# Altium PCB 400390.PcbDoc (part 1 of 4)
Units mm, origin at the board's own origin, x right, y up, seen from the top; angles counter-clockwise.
Board outline 50.8 x 50.4 mm, 4 copper layers (Top Layer, Mid Layer 1, Mid Layer 2, Bottom Layer), stack 1.507 mm thick; 236 components, 197 nets, 1131 pads, 994 vias.
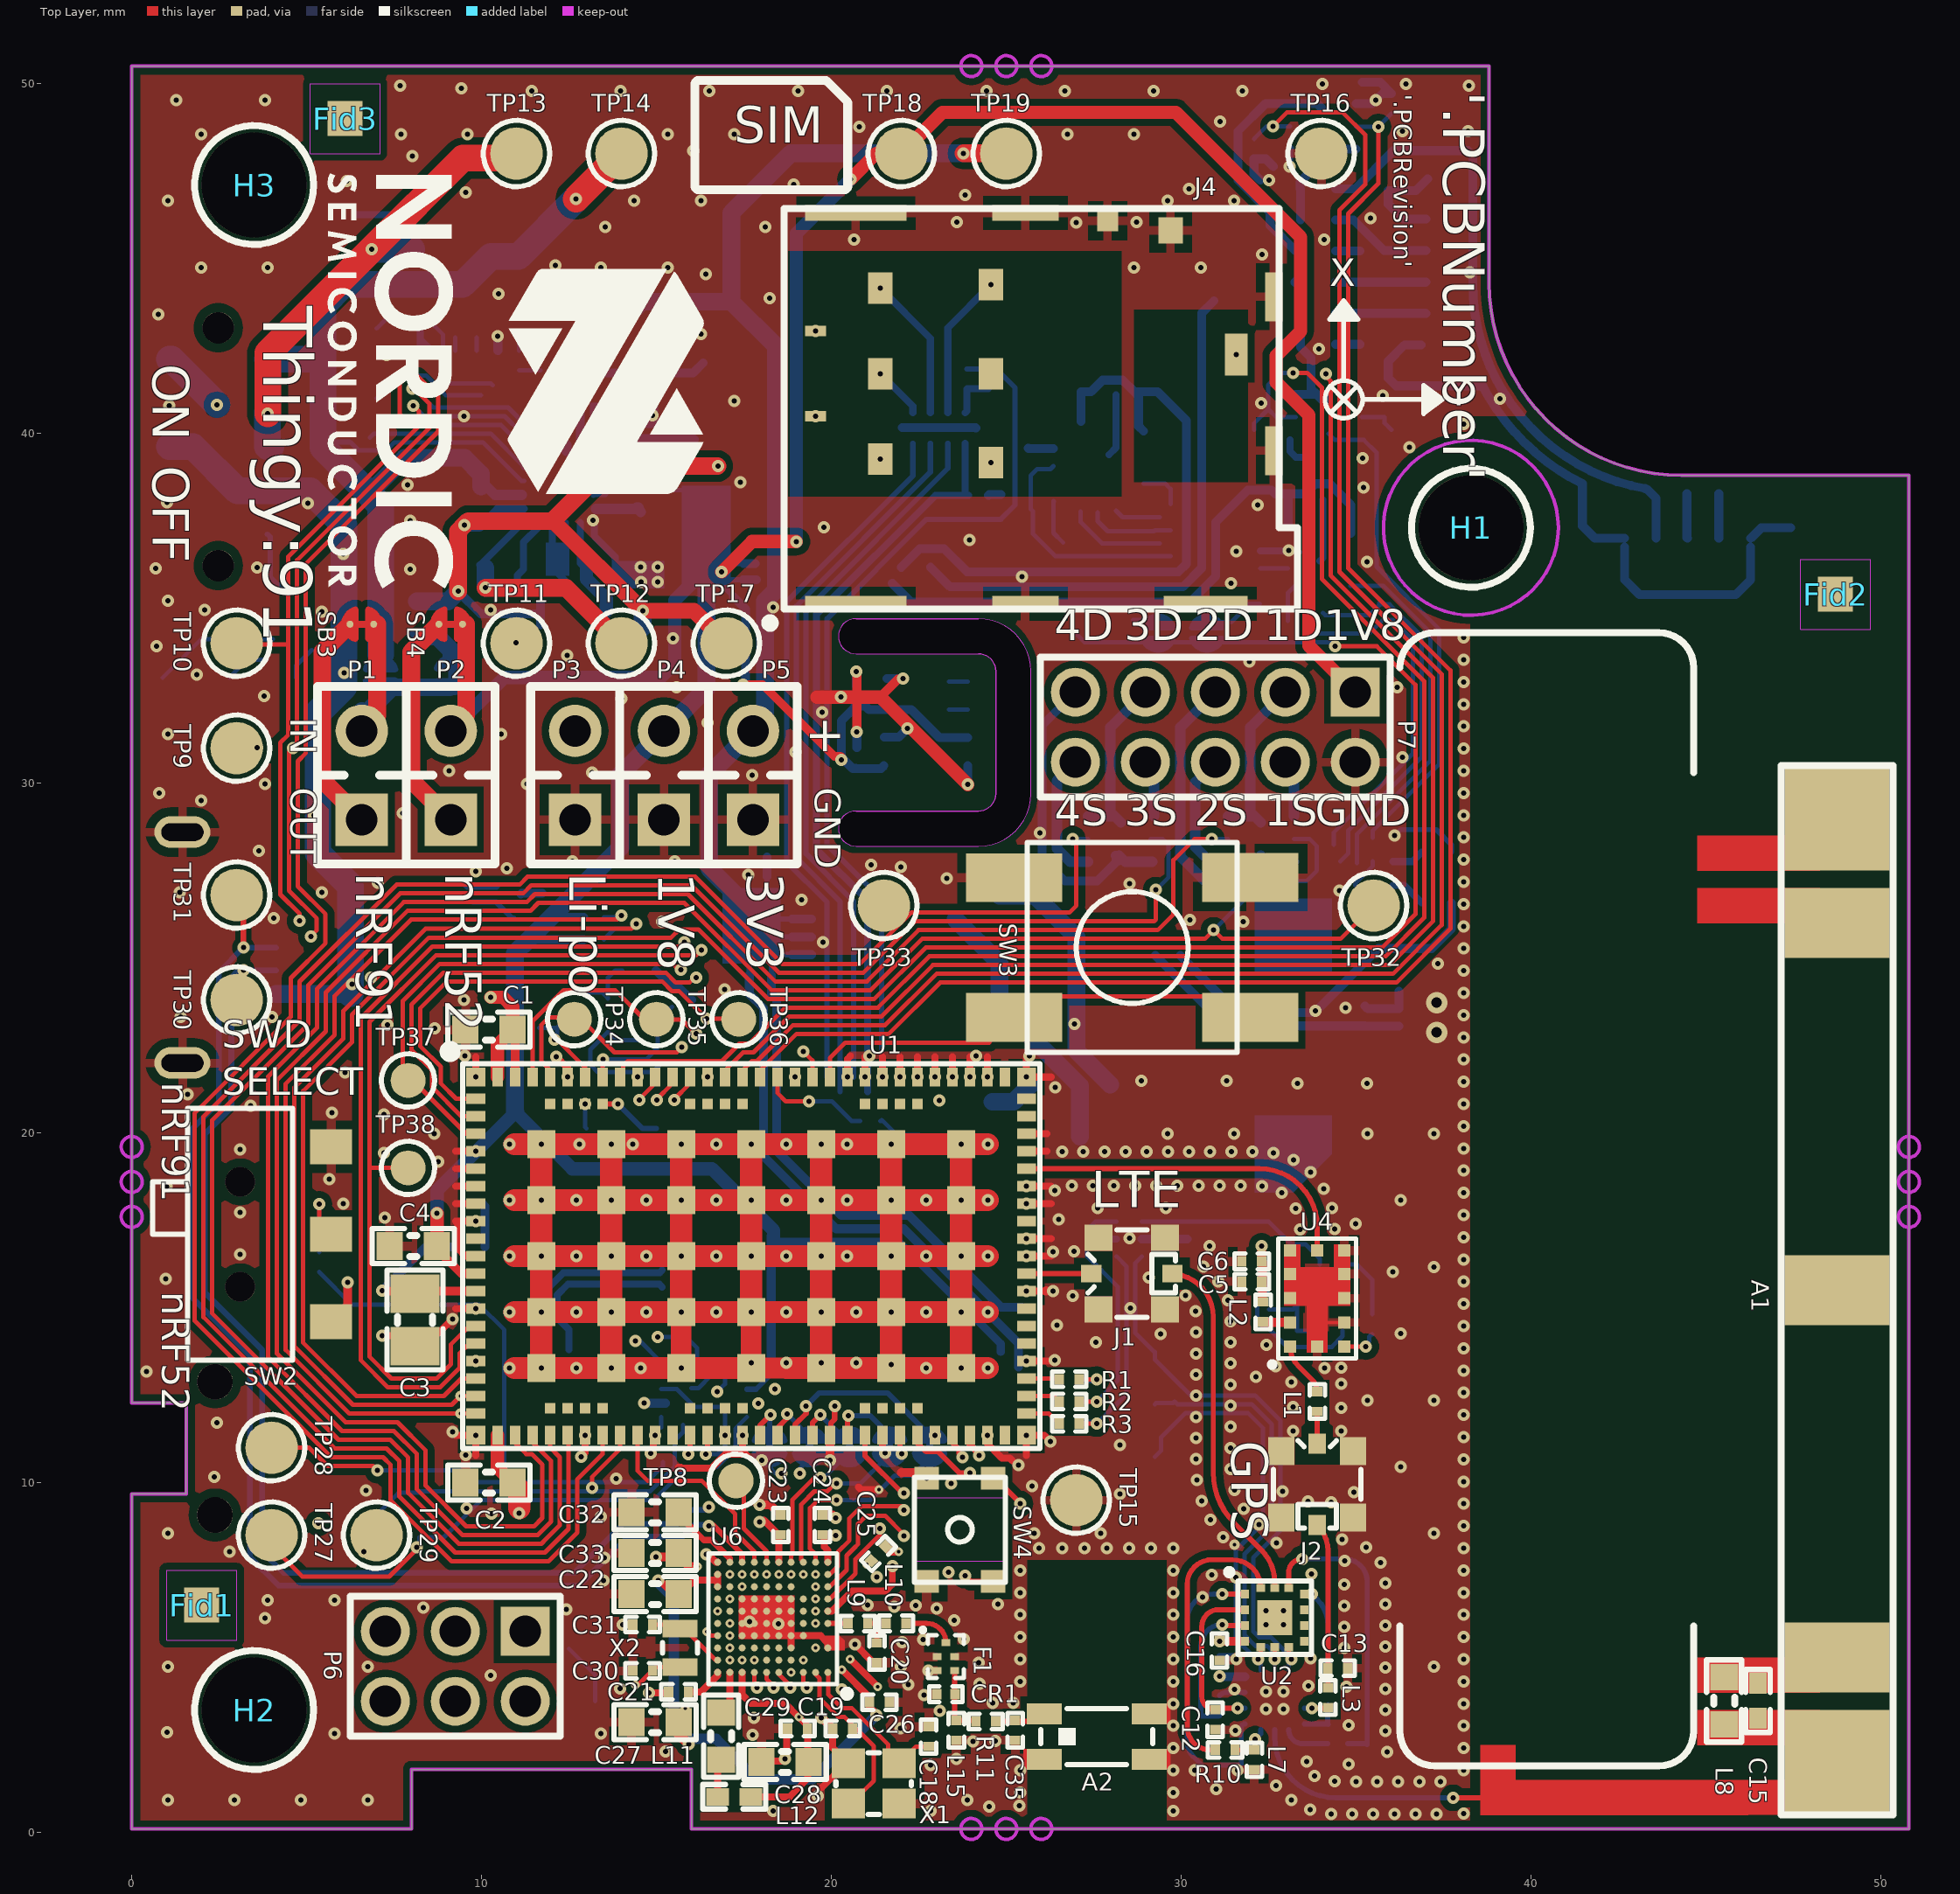
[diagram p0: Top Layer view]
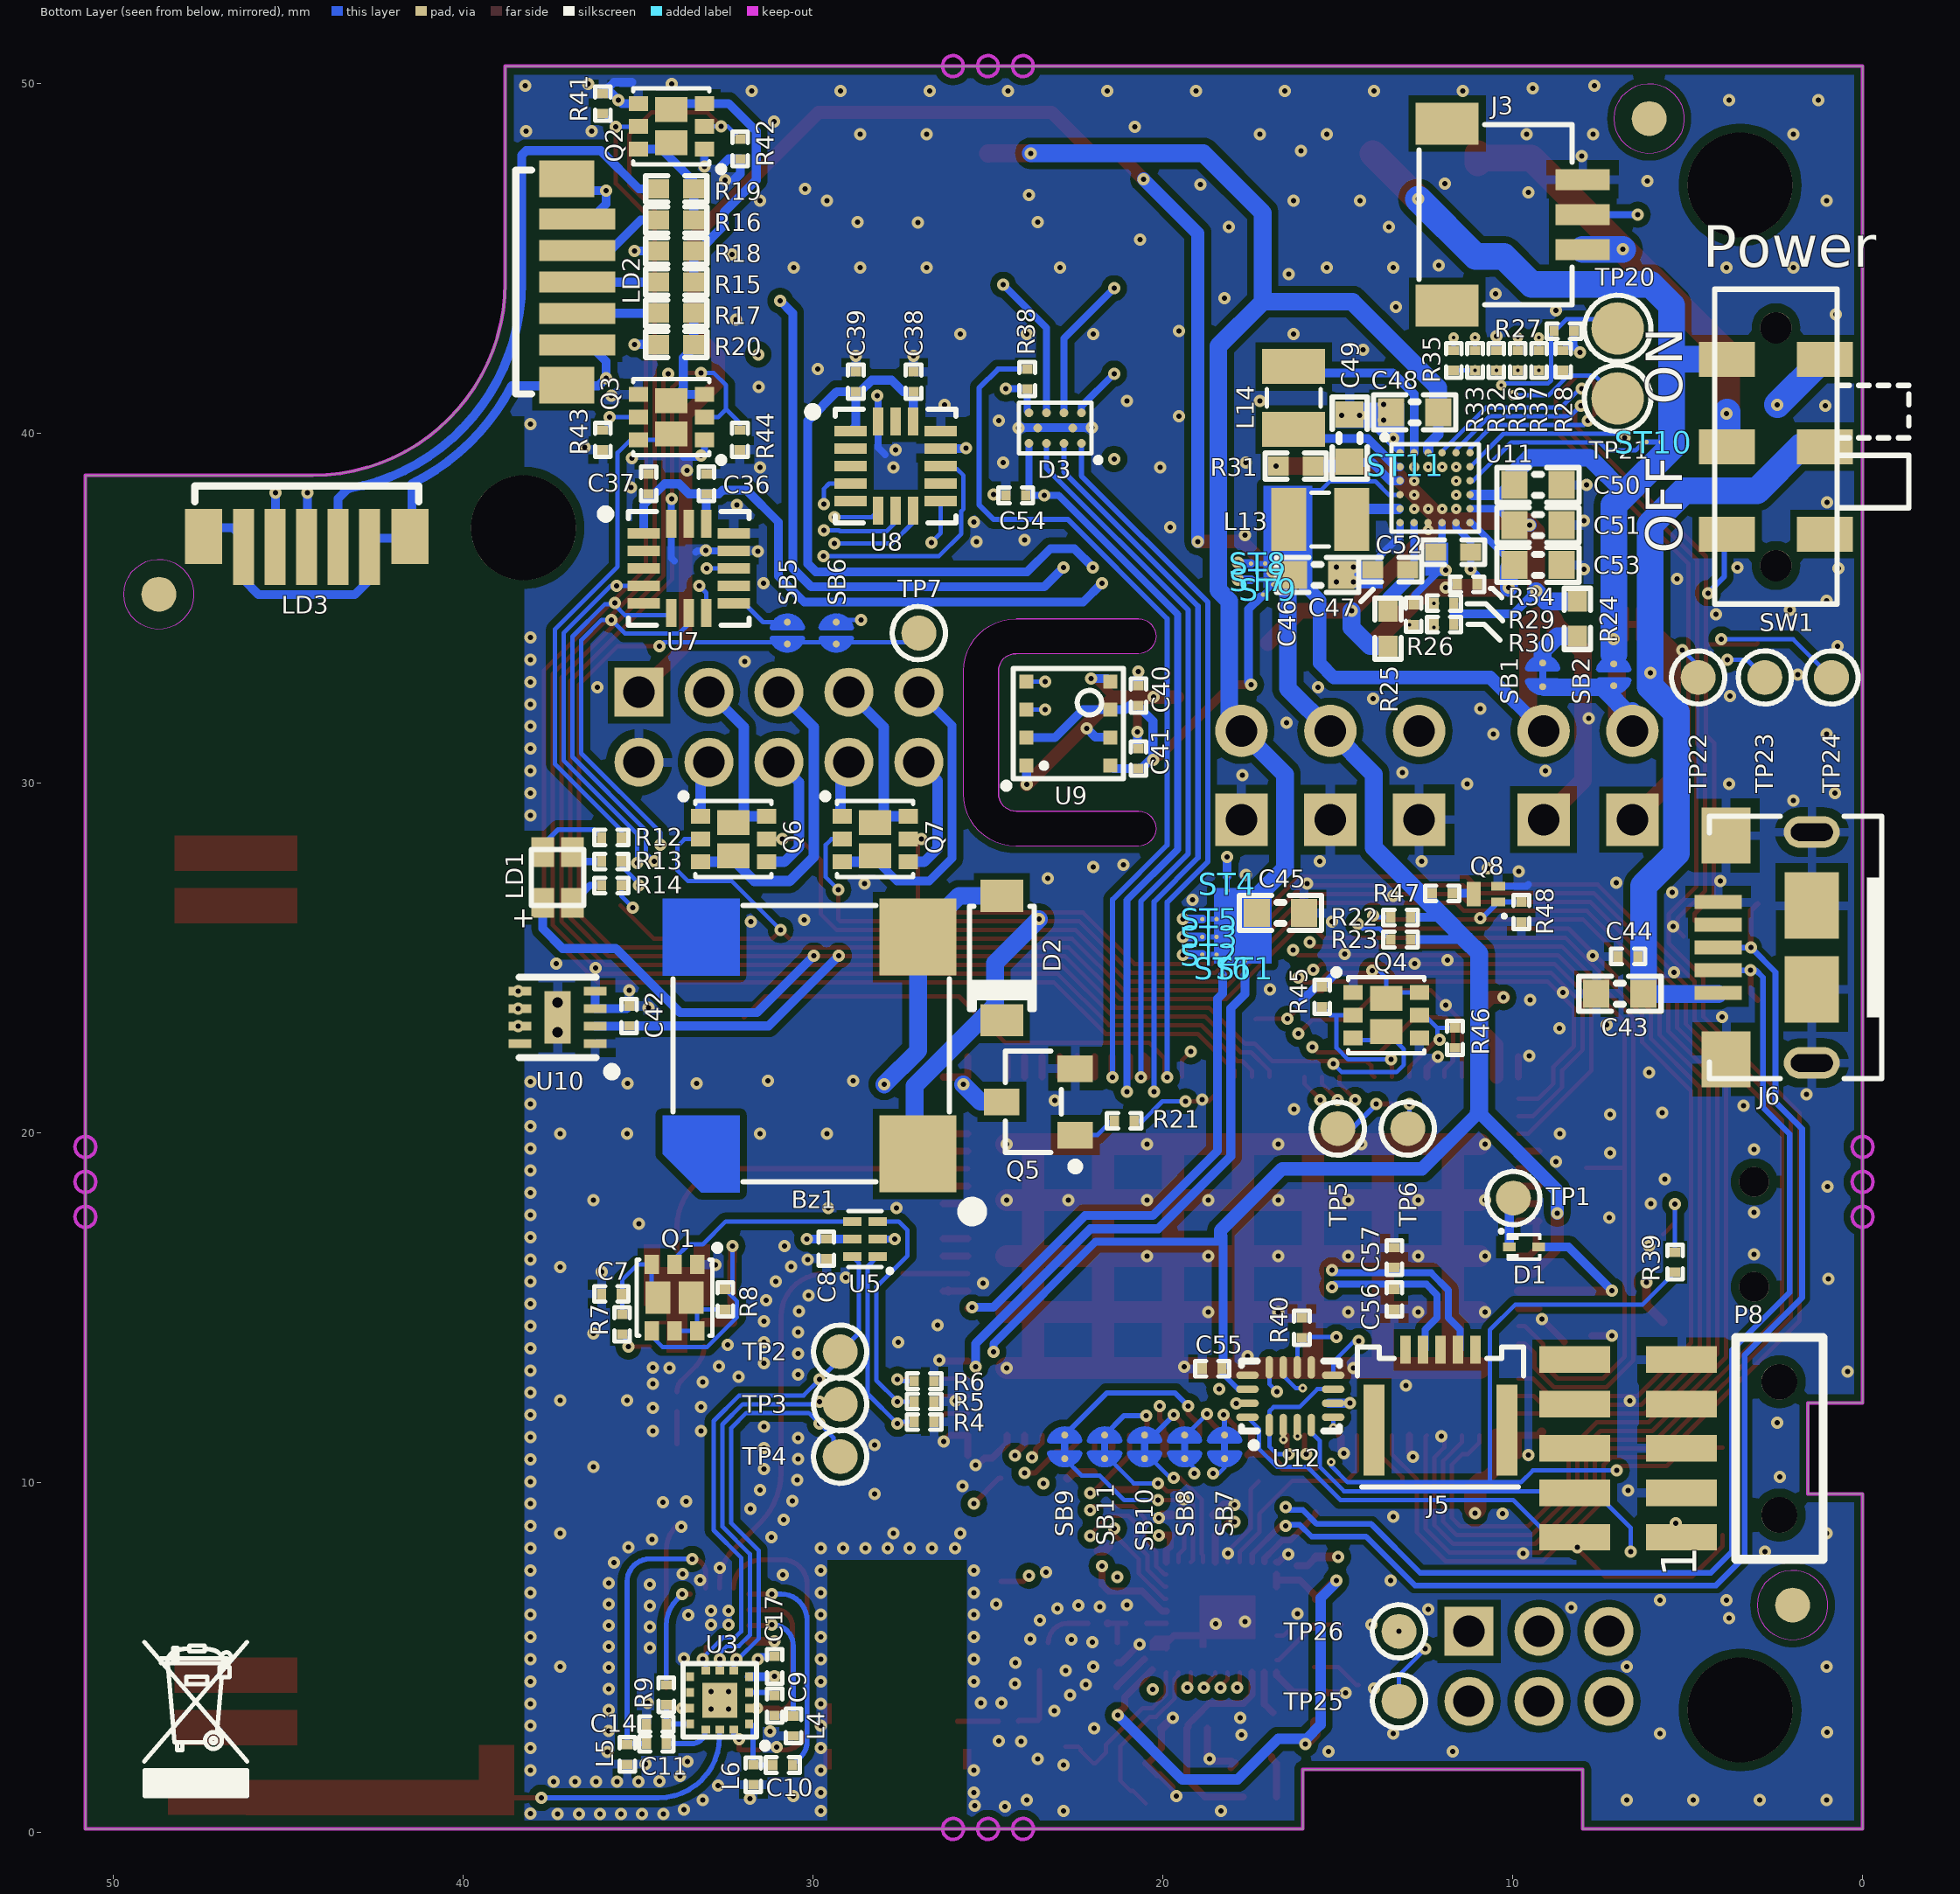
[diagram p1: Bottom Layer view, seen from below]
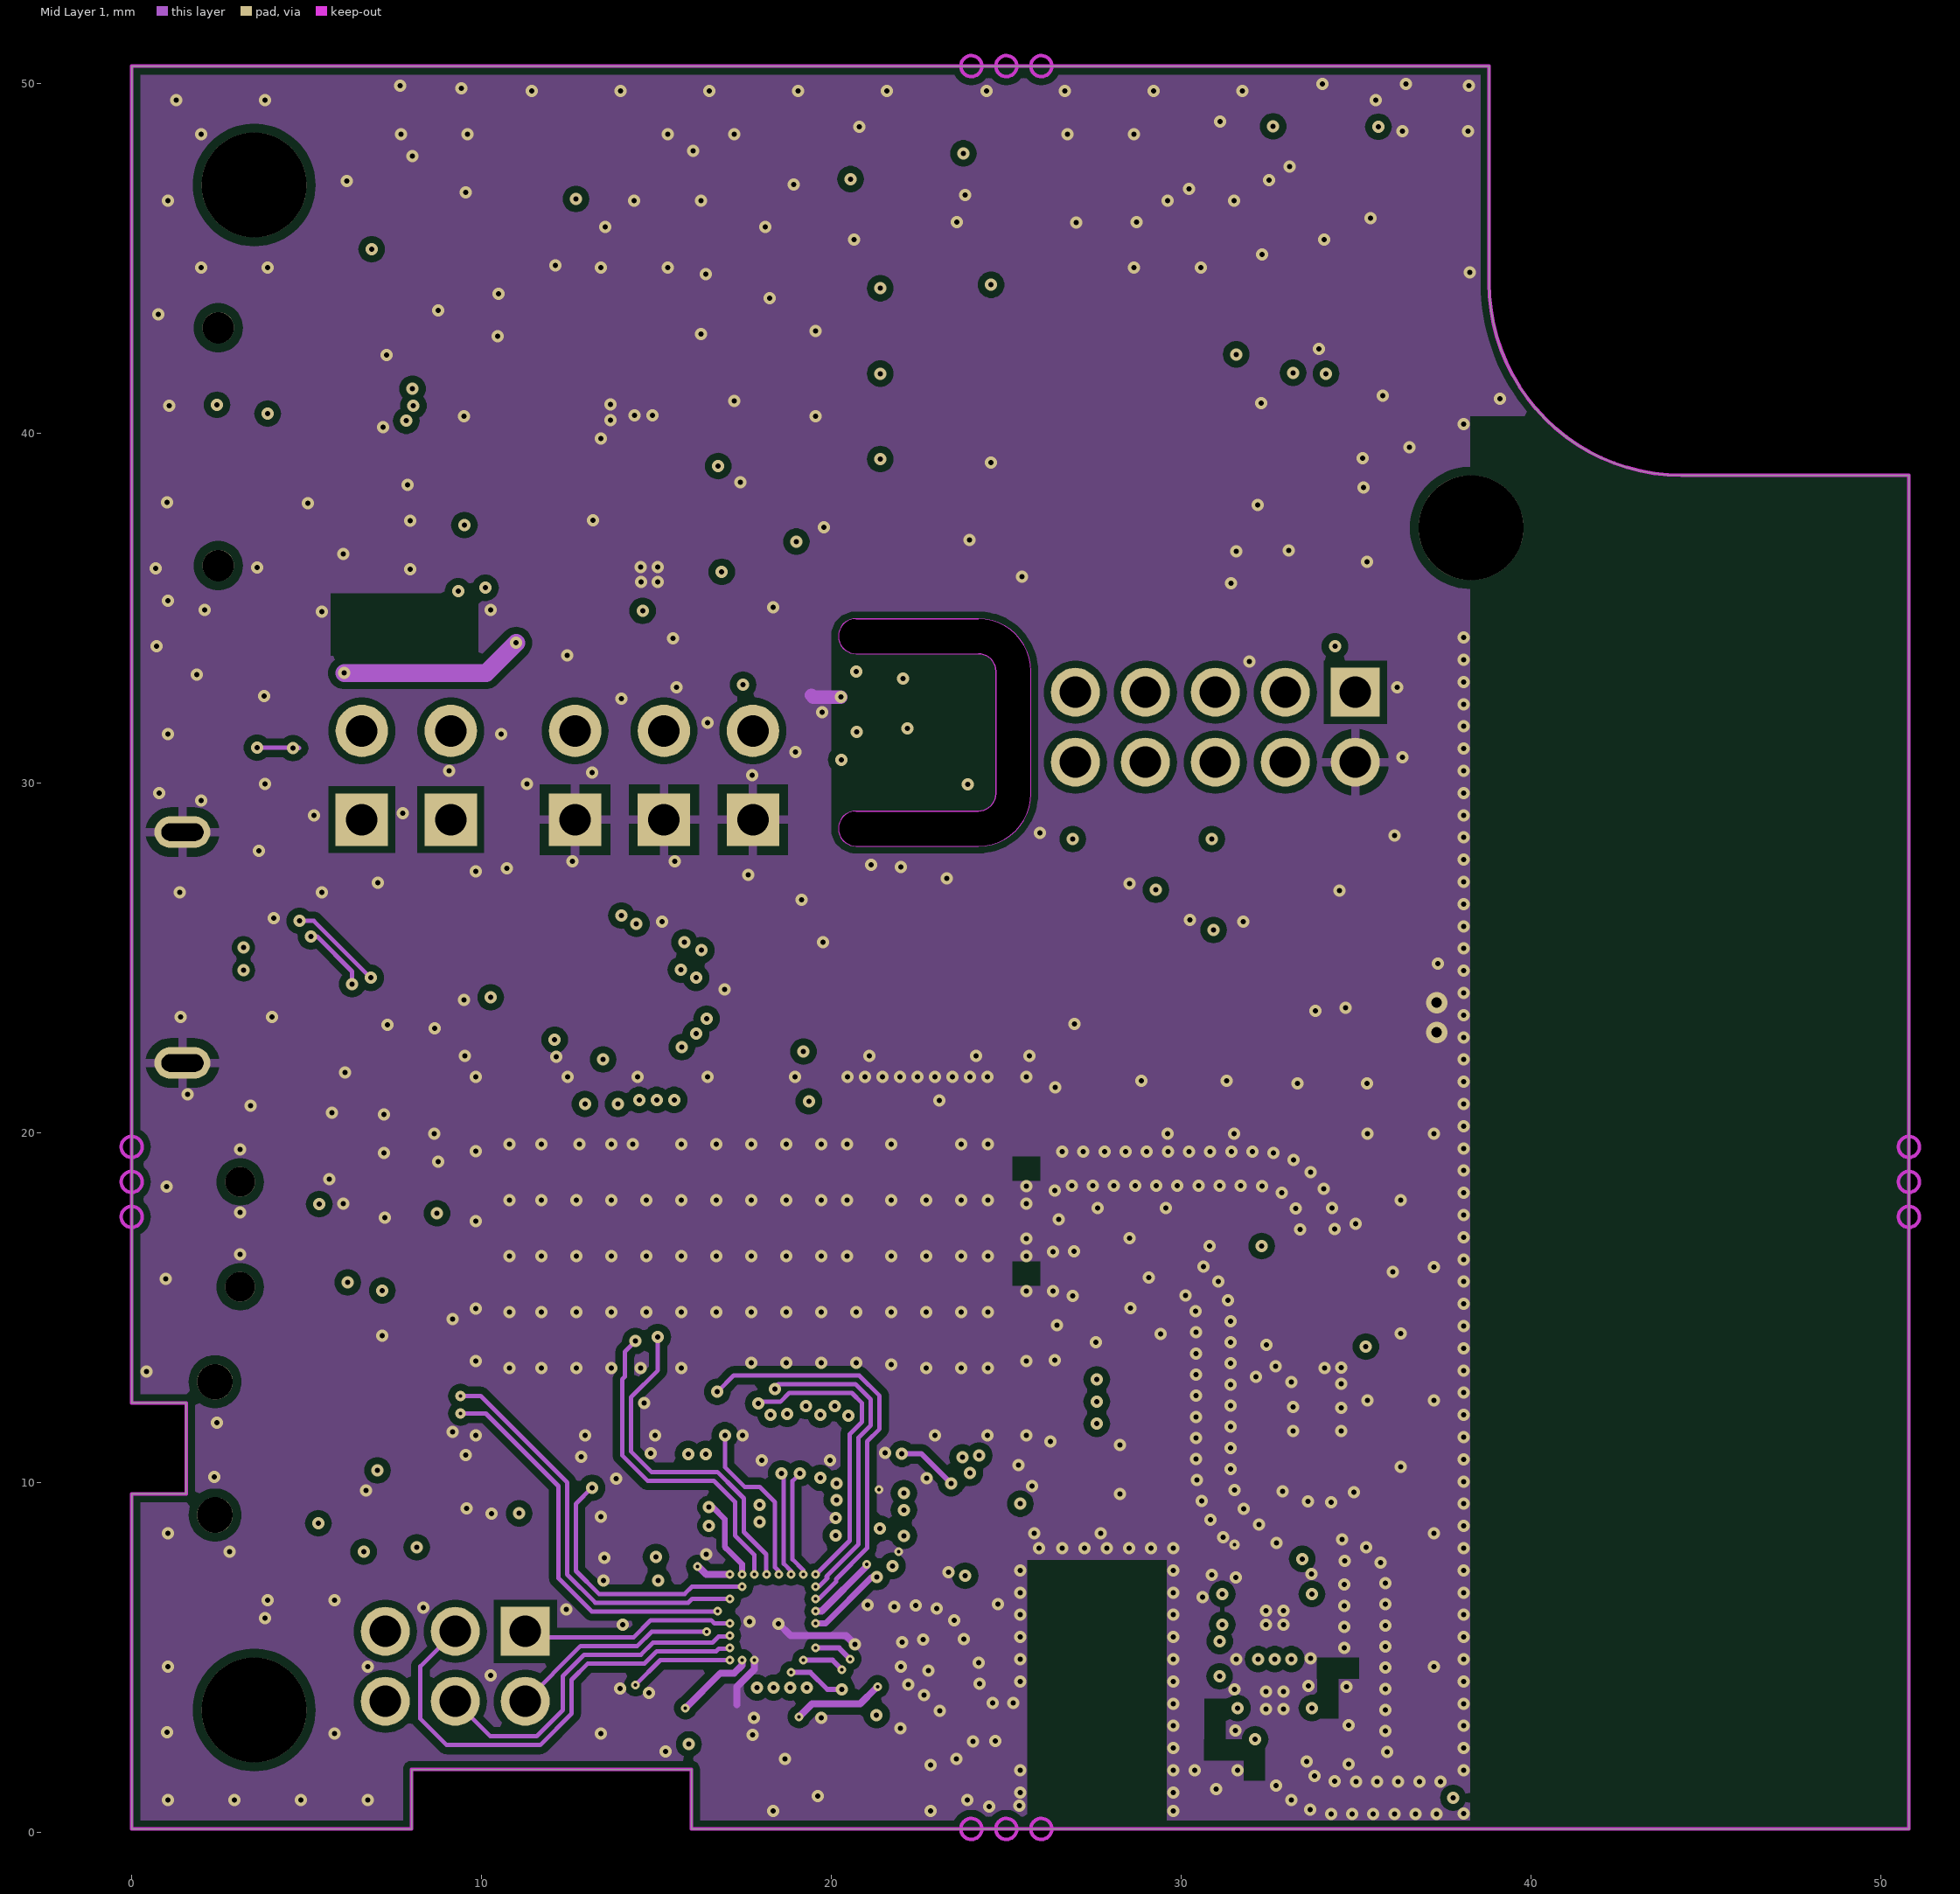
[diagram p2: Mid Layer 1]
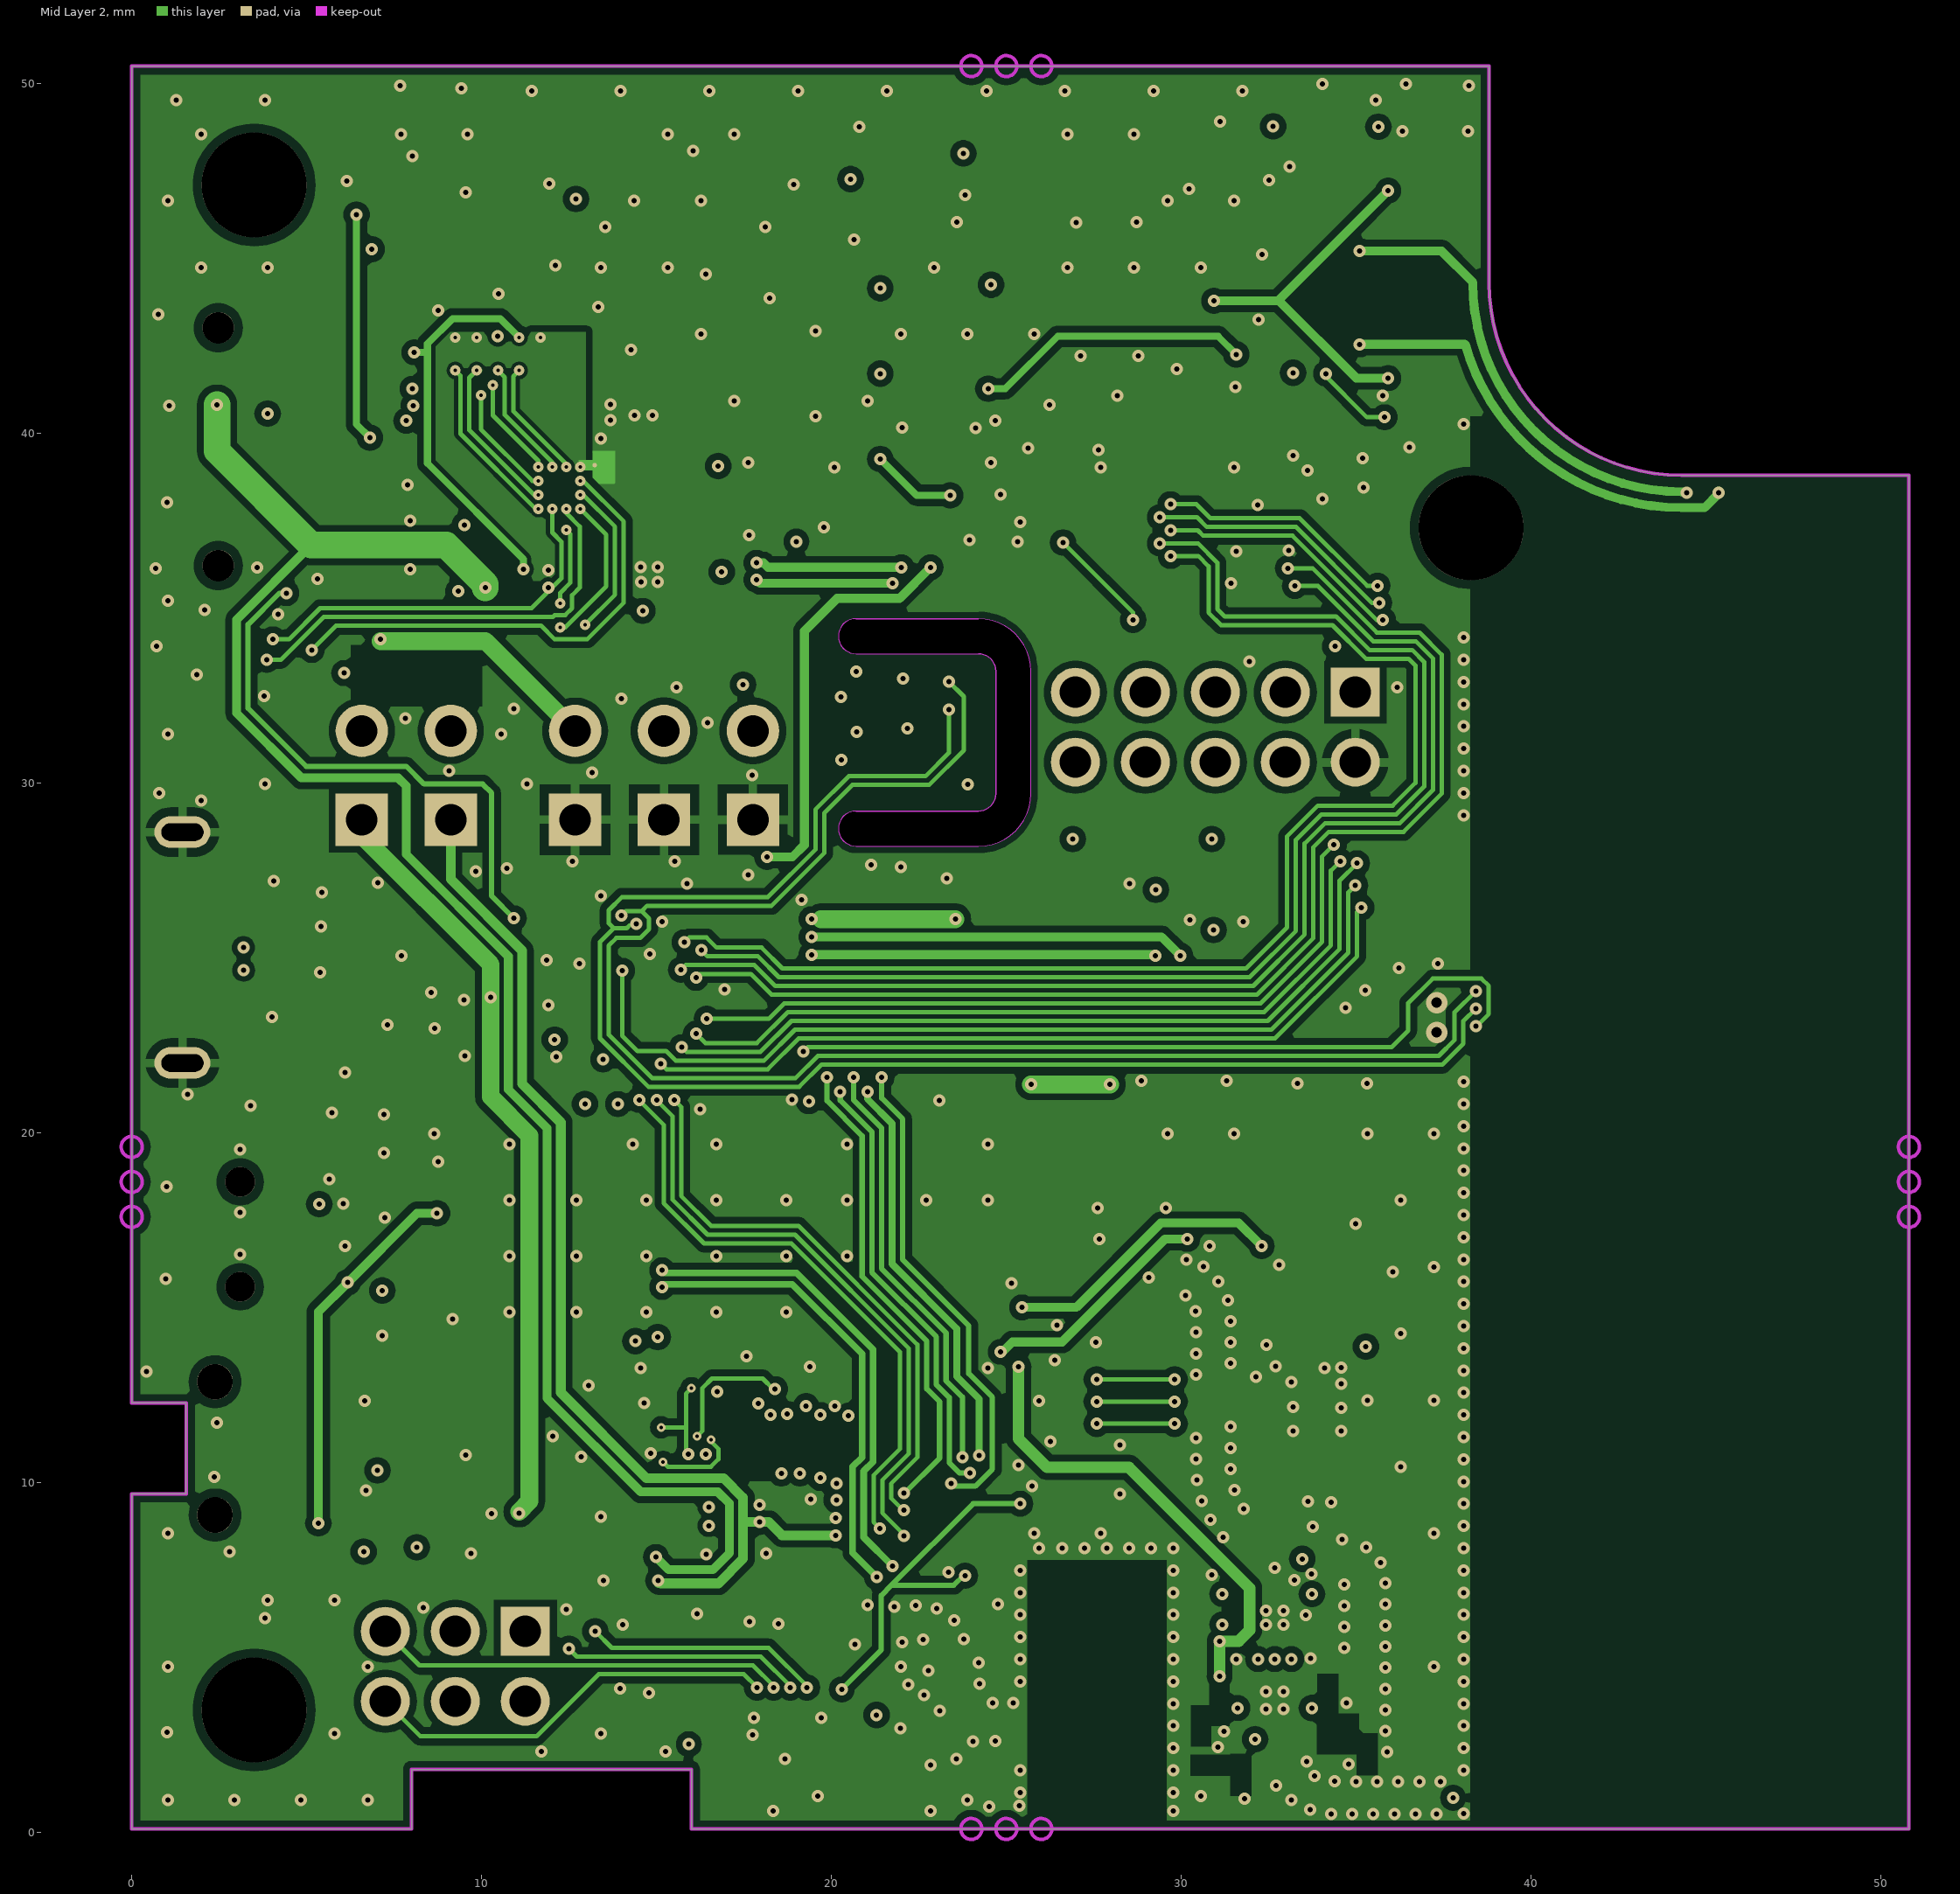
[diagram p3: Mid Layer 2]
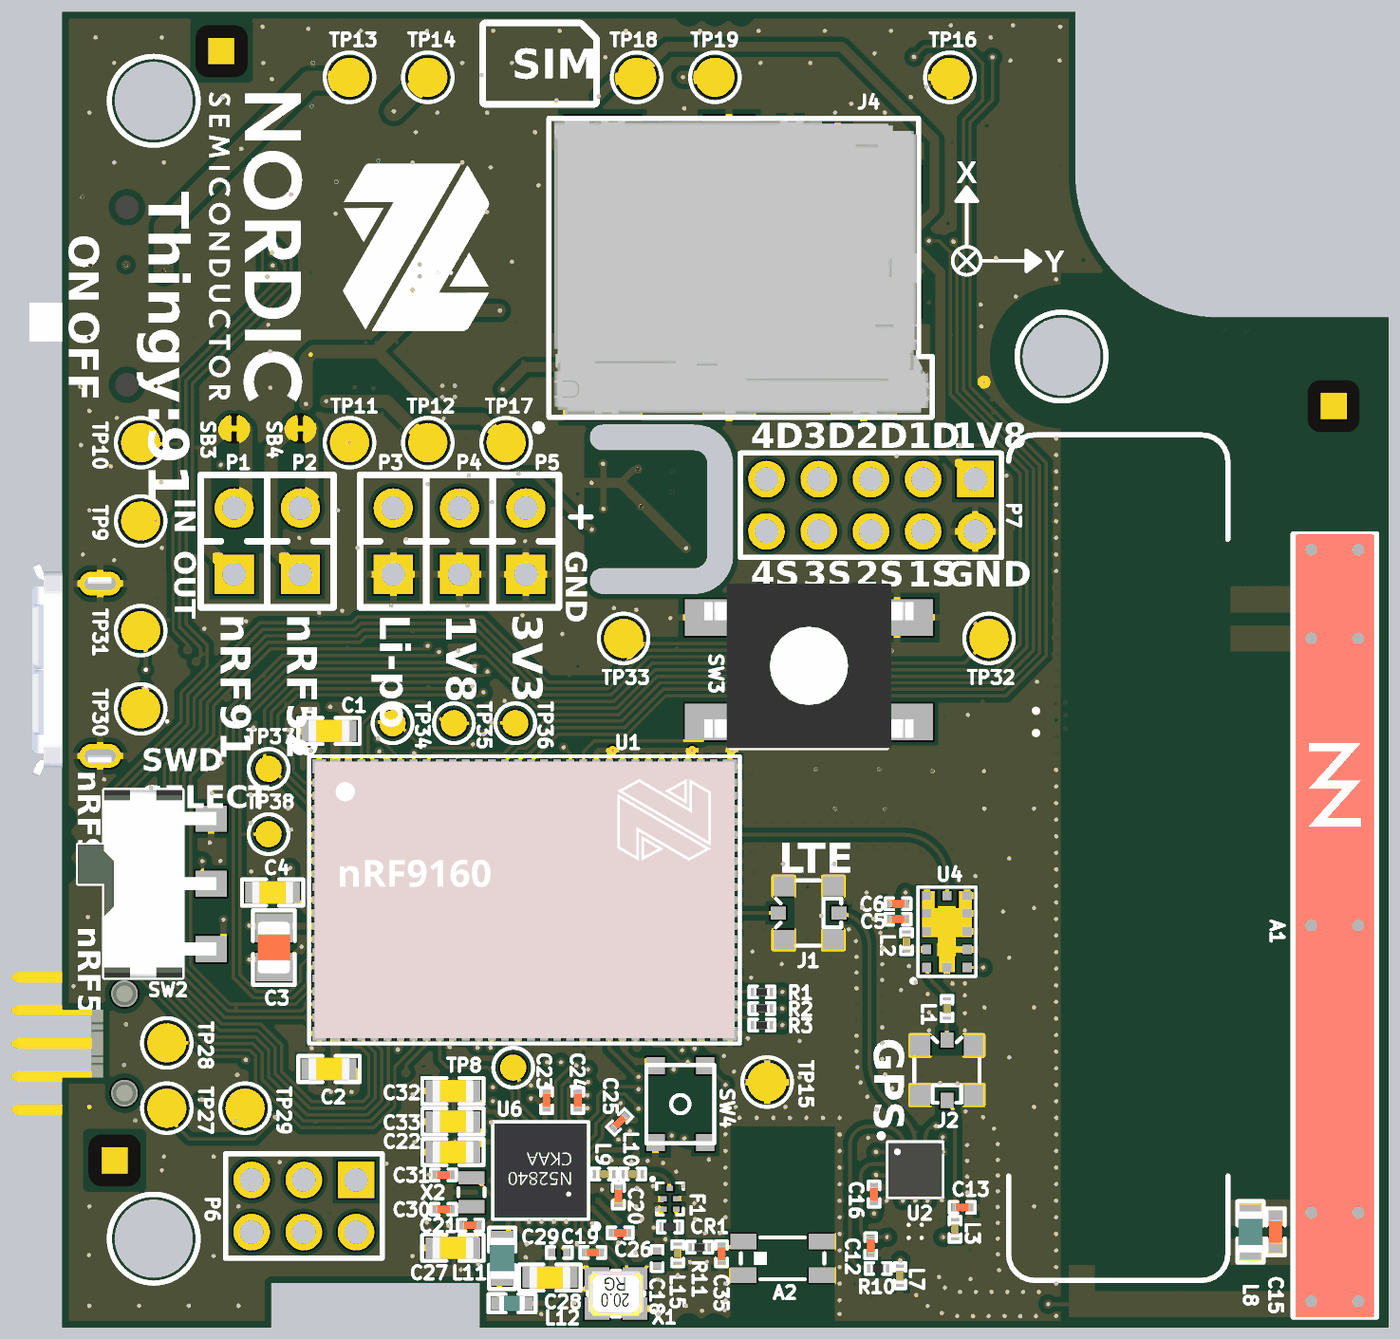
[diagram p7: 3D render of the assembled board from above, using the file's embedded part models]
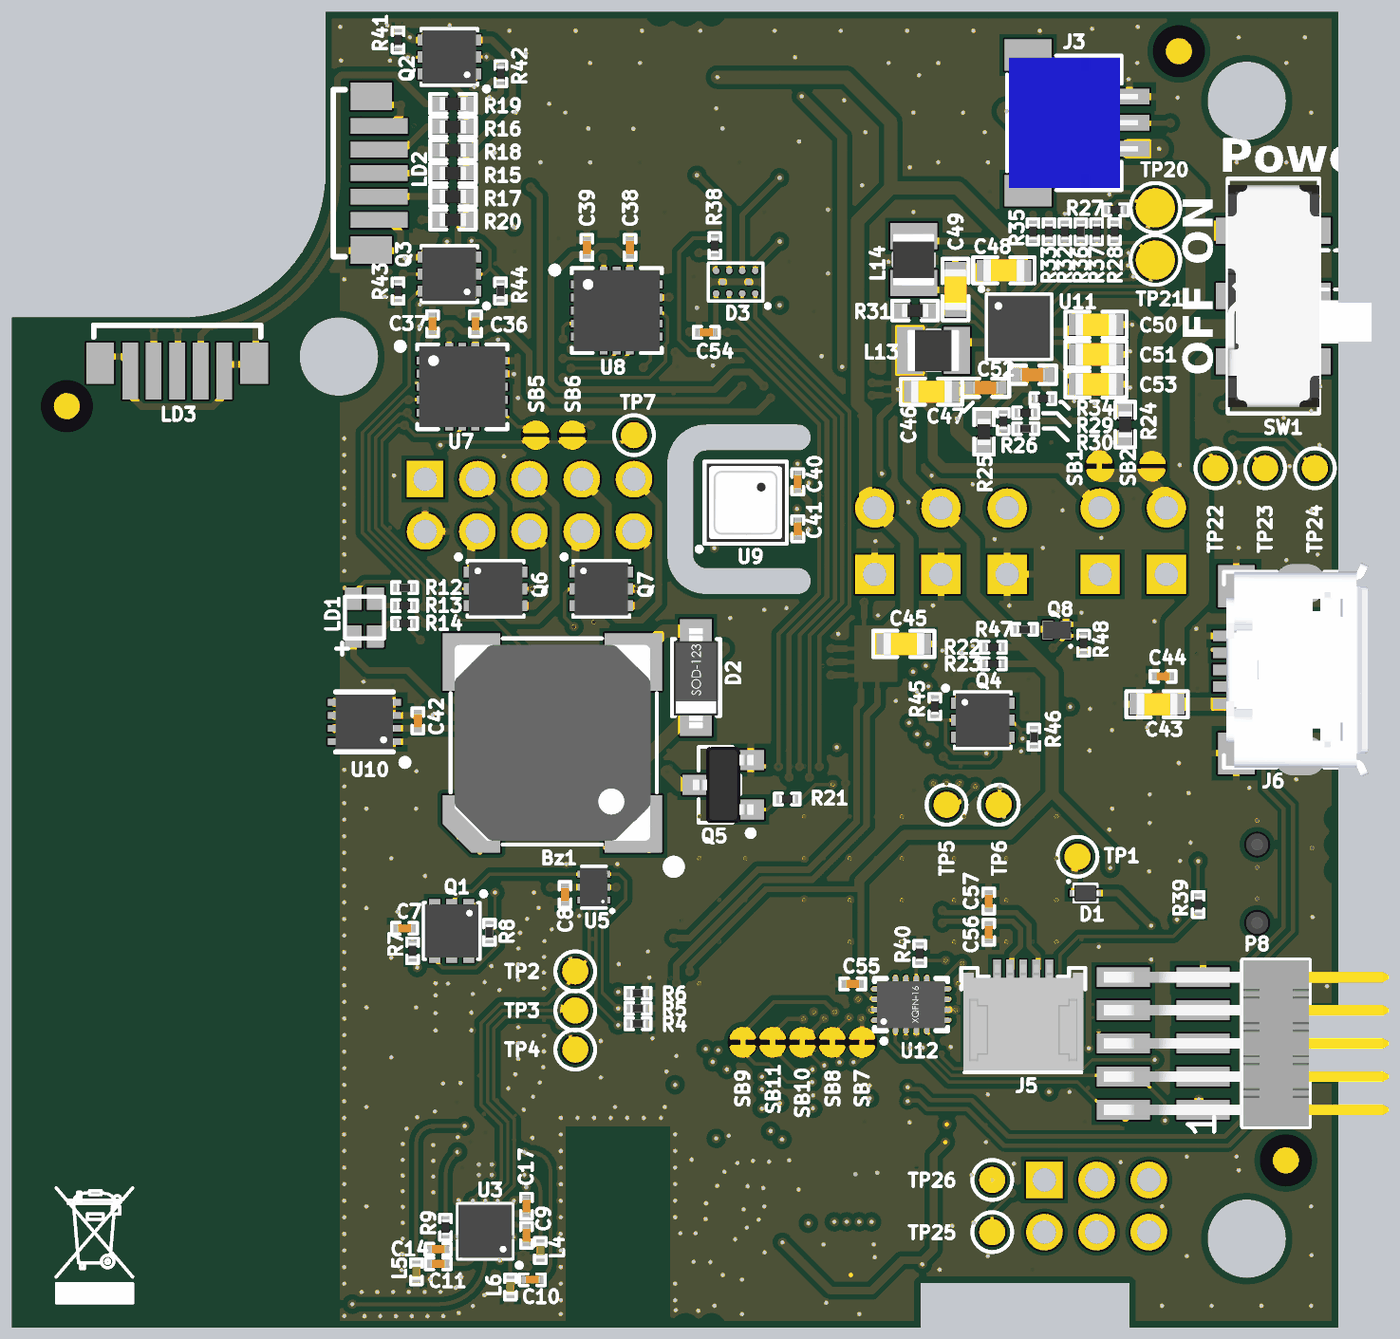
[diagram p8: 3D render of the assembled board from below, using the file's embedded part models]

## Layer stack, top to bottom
Top Solder: solder mask 0.0475, Solder Resist, Dk 3.5
Top Layer: signal copper 0.0175
Dielectric1: core 0.1, FR-4, Dk 4.8
Mid Layer 1: signal copper 0.036
Dielectric 3: prepreg 1.2, Dk 4.2
Mid Layer 2: signal copper 0.036
Dielectric 2: core 0.1, Dk 4.2
Bottom Layer: signal copper 0.0175
Bottom Solder: solder mask 0.0475, Solder Resist, Dk 3.5

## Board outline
0,0.1 0,9.68 1.56,9.68 1.56,12.28 0,12.28 0,50.5 38.8,50.5 38.8,44.3 ccw(c44.3,44.3) 44.3,38.8 50.8,38.8 50.8,0.1 16,0.1 16,1.8 8,1.8 8,0.1
cut-out: 20.7,33.7 24.2,33.7 cw(c24.2,33.2) 24.7,33.2 24.7,29.7 cw(c24.2,29.7) 24.2,29.2 20.7,29.2 ccw(c20.7,28.7) 20.2,28.7 ccw(c20.7,28.7) 20.7,28.2 24.2,28.2 ccw(c24.2,29.7) 25.7,29.7 25.7,33.2 ccw(c24.2,33.2) 24.2,34.7 20.7,34.7 ccw(c20.7,34.2) 20.2,34.2 ccw(c20.7,34.2) 20.7,33.7

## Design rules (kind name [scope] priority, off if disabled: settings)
Clearance USB_Poly_Clearance [(InNamedPolygon('Mid_Layer_1-GND')) vs (OnLayer('Mechanical 3'))] p1: gap=0.254 ignorepadtopadclearanceinfootprint=FALSE except(0: Arc-Hole Track-Hole SMDPad-Hole THPad-Hole Via-Hole Fill-Hole Poly-Hole Region-Hole Text-Hole)
Clearance "NPTH clearance" [Not PadIsPlated And HoleSize > 0] p2: gap=0.25 ignorepadtopadclearanceinfootprint=FALSE except(0: Arc-Hole Track-Hole SMDPad-Hole THPad-Hole Via-Hole Fill-Hole Poly-Hole Region-Hole Text-Hole)
Clearance "Keepout clearance" [All vs OnLayer('Keep-Out Layer')] p3: gap=0.2 ignorepadtopadclearanceinfootprint=FALSE
Clearance USB_Clearance [(InDifferentialPairClass('All Differential Pairs'))] p4: gap=0.15 ignorepadtopadclearanceinfootprint=FALSE except(0.1: Via-Via; 0.125: Arc-Via Track-Via SMDPad-Via)
Clearance ANT_Clerance [InNet('LTE_RF') or InNet('T1F') or InNet('T2F') or InNet('T3F') or InNet('T4F') or InNet('T5F') or InNet('T6F') or InNet('T1A') or InNet('T2A') or InNet('T3A') or InNet('T4A') or InNet('T5A') or InNet('T6A') or InNet('T7A') or InNet('ANT_GPS') or InNet('GPS_RF') or InNet('ANT_LTE')  or InNet('LTE_RF') or InNet('RF') or InNet('BLE_RF') or InNet('nRF52_ANT') or InNet('BLE_ANT') or InNet('GPS_LNA') or InNet('GPS_LNA_IN') vs (InNamedPolygon('Top_Layer-GND')) or (InNamedPolygon('Bottom_Layer-GND'))] p5: gap=0.206 ignorepadtopadclearanceinfootprint=FALSE
Clearance Polygon_Clearance [(InNamedPolygon('Top_Layer-GND')) or (InNamedPolygon('Bottom_Layer-GND')) or (InNamedPolygon('Mid_Layer_1-GND')) or (InNamedPolygon('Mid_Layer_2-GND'))] p6: gap=0.2 ignorepadtopadclearanceinfootprint=FALSE
Clearance SB_Clearance [HasFootprint('Solderbridge') or HasFootprint('QFN40P180X140X55-10N')] p7: gap=0.127 ignorepadtopadclearanceinfootprint=FALSE except(0: Arc-Hole Track-Hole SMDPad-Hole THPad-Hole Via-Hole Fill-Hole Poly-Hole Region-Hole Text-Hole)
Clearance CSP_Clearance [HasFootprint('BGA4C40P2X2_76X76X62')] p8: gap=0.127 ignorepadtopadclearanceinfootprint=FALSE except(0: Arc-Hole Track-Hole SMDPad-Hole THPad-Hole Via-Hole Fill-Hole Poly-Hole Region-Hole Text-Hole)
Clearance P23_Clearance [HasFootprint('FPC_05P-0.5mm-RA-SMD')] p9: gap=0.127 ignorepadtopadclearanceinfootprint=FALSE except(0: Arc-Hole Track-Hole SMDPad-Hole THPad-Hole Via-Hole Fill-Hole Poly-Hole Region-Hole Text-Hole)
Clearance 0.15mm_Clearance [HasFootprint('SOTFL50P162X60-6N') or HasFootprint('LGA50P200X200X80-10N') or HasFootprint('UFQFN40P200X200X65_HS-15N')] p10: gap=0.15 ignorepadtopadclearanceinfootprint=FALSE except(0: Arc-Hole Track-Hole SMDPad-Hole THPad-Hole Via-Hole Fill-Hole Poly-Hole Region-Hole Text-Hole)
Clearance µVia_Clearance [AsMM(HoleSize) = 0.1] p11: gap=0.1 ignorepadtopadclearanceinfootprint=FALSE
Clearance [All] p12: gap=0.125 ignorepadtopadclearanceinfootprint=FALSE
ComponentClearance [All] p1 off: gap=0.254 collisioncheckmode=3 verticalgap=0.254 showdistances=FALSE
DiffPairsRouting [All] p1: maxlimit=0.254 minlimit=0.004 mostfreqgap=0.193 toplayer_minwidth=0.15 toplayer_maxwidth=0.165 toplayer_prefwidth=0.165 midlayer1_minwidth=0.15 midlayer1_maxwidth=0.165 midlayer1_prefwidth=0.165 midlayer2_mingap=0.191 midlayer2_minwidth=0.165 midlayer2_maxwidth=0.165 midlayer2_prefwidth=0.165 bottomlayer_mingap=0.191 bottomlayer_minwidth=0.165 bottomlayer_maxwidth=0.165 bottomlayer_prefwidth=0.165 maxuncoupledlength=12.7
FabricationTestPointUsage TestPointUsage [All] p1: valid=0 allowmultiple=FALSE
FabricationTestpoint Testpoint [All] p1: side=3 testpointundercomponent=TRUE minsize=1.016 maxsize=2.54 preferedsize=1.524 minholesize=0 maxholesize=1.016 preferedholesize=0.813 testpointgrid=0.025 allowsidetop=TRUE allowsidebottom=TRUE usegrid=TRUE gridtolerance=0
Height [All] p1 off: minheight=0 maxheight=25.4 prefheight=12.7
HoleSize [All] p1: absolutevalues=TRUE maxlimit=5 minlimit=0.1 maxpercent=80.000 minpercent=20.000
MinimumAnnularRing [All] p1 off: minimumring=0.152
NetAntennae NetAntennae_ANT [InNet('ANT')] p1: netantennaetolerance=40
NetAntennae [All] p2: netantennaetolerance=0
PolygonConnect PolygonConnect_1 [isVia and (innet('GND') or InNet('AGND')) or HasFootprint('2450AT18D0100_STD-R') or HasFootprint('COAXIAL-SWF') or HasFootprint('2 PIN STARPOINT')] p1: connectstyle=Direct reliefconductorwidth=0.254 reliefentries=4 polygonreliefangle="90 Angle" airgapwidth=0.254
PolygonConnect [All] p2: connectstyle=Relief reliefconductorwidth=0.254 reliefentries=4 polygonreliefangle="90 Angle" airgapwidth=0.254
RoutingVias [All] p1: holewidth=0.15 width=0.35 viastyle="Through Hole" minholewidth=0.1 minwidth=0.25 maxholewidth=0.305 maxwidth=0.61
ShortCircuit ShortCircuit_AGND/GND [InNet('AGND') vs InNet('GND')] p1: allowed=TRUE
ShortCircuit [All] p2: allowed=FALSE
SilkToSolderMaskClearance SilkscreenOverComponentPads [IsPad] p1: minsilkscreentomaskgap=0.254 clearancetoexposedcopper=TRUE
SolderMaskExpansion [All] p1: expansion=0.076
UnpouredPolygon [All] p1 off:
Width Width_Diff [(InDifferentialPairClass('All Differential Pairs'))] p1: maxlimit=0.165 minlimit=0.165 preferedwidth=0.165
Width [All] p2: maxlimit=10.16 minlimit=0.125 preferedwidth=0.152 minimp=50.000000 maximp=50.000000 favimp=50.000000
20 further rules are at their usual default settings.

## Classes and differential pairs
differential pair D: +D_P -D_N

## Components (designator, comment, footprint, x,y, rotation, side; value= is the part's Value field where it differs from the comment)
A1 "FR01-S4-210" FR01-S4-210_DF 48.75,15.5 r270 top locked
A2 "2450AT18D0100" 2450AT18D0100_STD-R 27.591,2.743 r180 top locked
Bz1 "Buzzer" Buzzer_SMD_7.5x7.5 30.1,22.5 r0 bottom
C1 "4.7µF" CAPC1608X06L 10.213,22.954 r0 top
C2 "4.7µF" CAPC1608X06L 10.213,10 r0 top
C3 "47µF" CAPC2012X11L 8.103,14.656 r270 top
C4 "4.7µF" CAPC1608X06L 8.052,16.764 r180 top
C5 "100pF" CAPC0603X03L_C 32.016,15.744 r0 top
C6 "100nF" CAPC0603X03L_C 32.016,16.328 r0 top
C7 "6.8pF" CAPC0603X03L_C 35.763,15.392 r180 bottom
C8 "100nF" CAPC0603X03L_C 29.616,16.688 r90 bottom
C9 "2.5pF" CAPC0603X03L_C 31.096,3.629 r270 bottom
C10 "5.5pF" CAPC0603X03L_C 30.868,1.927 r180 bottom
C11 "9.2pF" CAPC0603X03L_C 34.474,2.537 r0 bottom
C12 "1.5pF" CAPC0603X03L_C 30.969,3.223 r90 top
C13 "3.9pF" CAPC0603X03L_C 34.474,4.696 r180 top
C14 "3.1pF" CAPC0603X03L_C 34.474,3.096 r180 bottom
C15 "0.3pF" CAPC1005X04L 46.482,3.759 r90 top
C16 "2.2nF" CAPC0603X03L_C 31.096,5.204 r90 top
C17 "2.2nF" CAPC0603X03L_C 31.096,4.747 r270 bottom
C18 "12pF" CAPC0603X03L_C 22.784,2.743 r90 top
C19 "12pF" CAPC0603X03L_C 20.32,2.97 r180 top
C20 "1.0pF" CAPC0603X03L_C 21.301,5.138 r90 top
C21 "100nF" CAPC0603X03L_C 15.63,4.017 r180 top
C22 "4.7µF" CAPC1608X06L 14.963,6.818 r180 top
C23 "100nF" CAPC0603X03L_C 18.55,8.793 r90 top
C24 "100nF" CAPC0603X03L_C 19.745,8.793 r90 top
C25 "820pF" CAPC0603X03L_C 21.346,7.973 r45 top
C26 "100nF" CAPC0603X03L_C 21.373,3.723 r0 top
C27 "1.0µF" CAPC1608X06L 14.961,3.15 r180 top
C28 "1.0µF" CAPC1608X06L 18.678,2.011 r0 top
C29 "47nF" CAPC0603X03L_C 19.033,2.97 r180 top
C30 "12pF" CAPC0603X03L_C 14.605,4.623 r180 top
C31 "12pF" CAPC0603X03L_C 14.605,5.944 r180 top
C32 "4.7µF" CAPC1608X06L 14.963,9.155 r180 top
C33 "4.7µF" CAPC1608X06L 14.963,7.987 r180 top
C35 "0.8pF" CAPC0603X03L_C 25.25,2.921 r270 top
C36 "100nF" CAPC0603X03L_C 33.045,38.557 r270 bottom
C37 "100nF" CAPC0603X03L_C 34.696,38.557 r270 bottom
C38 "100nF" CAPC0603X03L_C 27.127,41.478 r270 bottom
C39 "100nF" CAPC0603X03L_C 28.778,41.478 r270 bottom
C40 "100nF" CAPC0603X03L_C 20.7,32.5 r270 bottom
C41 "100nF" CAPC0603X03L_C 20.7,30.7 r270 bottom
C42 "100nF" CAPC0603X03L_C 35.255,23.343 r270 bottom
C43 "10µF" CAPC1608X06L 6.934,23.978 r0 bottom
C44 "100nF" CAPC0603X03L_C 6.706,25.044 r0 bottom
C45 "4.7µF" CAPC1608X06L 16.637,26.289 r0 bottom
C46 "22µF" CAPC1608X06L 15.576,35.956 r0 bottom
C47 "1.0µF" CAPC1005X04L 13.501,36.106 r180 bottom
C48 "22µF" CAPC1608X06L 12.805,40.605 r180 bottom
C49 "1.0µF" CAPC1608X06L 14.659,39.868 r270 bottom
C50 "4.7µF" CAPC1608X06L 9.274,38.522 r0 bottom
C51 "10µF" CAPC1608X06L 9.274,37.379 r0 bottom
C52 "1.0µF" CAPC1005X04L 11.701,36.601 r180 bottom
C53 "2.2µF" CAPC1608X06L 9.274,36.236 r0 bottom
C54 "10nF" CAPC0603X03L_C 24.206,38.227 r0 bottom
C55 "100nF" CAPC0603X03L_C 18.593,13.259 r0 bottom
C56 "560pF" CAPC0603X03L_C 13.386,15.24 r270 bottom
C57 "560pF" CAPC0603X03L_C 13.386,16.434 r270 bottom
CR1 "LXES03AAA1-154" LXES03AAA1-154 23.275,3.95 r0 top
D1 "NSR0620P2T5G" SODFL100X40-2N 9.677,16.739 r180 bottom
D2 "1N4148W" SOD-123-DIODE 24.6,25 r90 bottom
D3 "CM1402" CM1402 23.078,40.152 r0 bottom
F1 "SAFFB2G45MA0F0A" SAFFB2G45MA0F0A 23.275,5.025 r270 top
Fid1 "Fiducial mark" Fiducial_Round-Square 2,6.5 r0 top
Fid2 "Fiducial mark" Fiducial_Round-Square 48.7,35.4 r0 top
Fid3 "Fiducial mark" Fiducial_Round-Square 6.1,49 r90 top
H1 "3mm,N.P" HOLE_NP_3MM 38.28,37.3 r180 top locked
H2 "3mm,N.P" HOLE_NP_3MM 3.5,3.5 r0 top
H3 "3mm,N.P" HOLE_NP_3MM 3.5,47.1 r270 top
J1 "MM8130-2600" COAXIAL-SWF 28.589,15.977 r90 top
J2 "MM8130-2600" COAXIAL-SWF 33.888,9.954 r0 top
J3 "HDR-3, 1mm" SM03B-SRSS-TB 8,46.258 r270 bottom locked
J4 "SF72S006VBAR2500" SF72S006VBAR2500 18.794,35.128 r270 top locked
J5 "FPC 0.5mm RA SMD" FPC_05P-0.5mm-RA-SMD 13.06,13.8 r180 bottom
J6 "MicroUSB-B" USB-Micro-B-RA-SMD-PiP 4.125,25.3 r0 bottom locked
L1 "3.3nH" INDC0603X03L_C 33.888,12.319 r270 top
L2 "5.6nH" INDC0603X03L_C 32.338,14.884 r90 top
L3 "2.9nH" INDC0603X03L_C 34.195,3.858 r270 top
L4 "N.C." INDC0603X03L_C 30.563,3.045 r90 bottom
L5 "6.2nH" INDC0603X03L_C 35.313,2.232 r90 bottom
L6 "5.1nH" INDC0603X03L_C 31.706,1.648 r90 bottom
L7 "4.7nH" INDC0603X03L_C 32.087,2.08 r90 top
L8 "15nH" INDC1608X06L 45.517,3.759 r90 top
L9 "3.9nH" INDC0603X03L_C 20.755,5.976 r0 top
L10 "4.7nH" INDC0603X03L_C 21.847,5.976 r0 top
L11 "10µH" INDC1608X06L 16.849,2.747 r90 top
L12 "15nH" INDC1005X04L 17.224,1.02 r180 top
L13 "2.2µH" INDC2016X18N 15.404,37.535 r0 bottom
L14 "2.2µH" INDC2016X18N 16.259,40.914 r90 bottom
L15 "2.7nH" INDC0603X03L_C 23.574,2.921 r270 top
LD1 "LED RGB" LED_RGB_0606 37.3,27.3 r180 bottom locked
LD2 "LED RGB" MSL0104 36.742,44.328 r90 bottom locked
LD3 "LED RGB" MSL0104 44.475,36.75 r180 bottom locked
P1 "Pin List 1x2" LIST_1x2-NC 6.579,30.226 r90 top locked
P2 "Pin List 1x2" LIST_1x2-NC 9.119,30.226 r90 top locked
P3 "Pin List 1x2" LIST_1x2-NC 12.675,30.226 r90 top locked
P4 "Pin List 1x2" LIST_1x2-NC 15.215,30.226 r90 top locked
P5 "Pin List 1x2" LIST_1x2-NC 17.755,30.226 r90 top locked
P6 "Pin Header 2x3, 2.00mm" HDR_2x3_TH_2.00MM-NC 9.25,4.75 r180 top
P7 "Pin Header 2x5, 2.00mm" HDR_2x5_TH_2.00MM-NC 30.975,31.6 r180 top locked
P8 "Pin Header 2x5" HDR_2x5-SMD-1.27mm-ANG 6.7,10.98 r90 bottom locked
Q1 "TSM2537CQ RFG" DFN65P200X200X80_HS-6N 33.96,15.291 r270 bottom
Q2 "TSM250N02DCQ RFG" DFN65P200X200X80_HS-6N 34.051,48.781 r0 bottom
Q3 "TSM250N02DCQ RFG" DFN65P200X200X80_HS-6N 34.051,40.462 r0 bottom
Q4 "TSM250N02DCQ RFG" DFN65P200X200X80_HS-6N 13.614,23.368 r180 bottom
Q5 "BC847C" SOT-23a 22.504,19.939 r90 bottom
Q6 "TSM250N02DCQ RFG" DFN65P200X200X80_HS-6N 32.275,28.4 r180 bottom
Q7 "TSM250N02DCQ RFG" DFN65P200X200X80_HS-6N 28.225,28.4 r180 bottom
Q8 "RV2C010UNT2L" DFN65P100X40-3L 10.77,26.822 r0 bottom
R1 "1k" RESC0603X03L_C 26.797,12.954 r0 top
R2 "1k" RESC0603X03L_C 26.797,12.319 r0 top
R3 "1k" RESC0603X03L_C 26.797,11.684 r0 top
R4 "1M0" RESC0603X03L_C 26.822,11.735 r0 bottom
R5 "1M0" RESC0603X03L_C 26.822,12.319 r0 bottom
R6 "1M0" RESC0603X03L_C 26.822,12.903 r0 bottom
R7 "3k" RESC0603X03L_C 35.458,14.529 r90 bottom
R8 "1M0" RESC0603X03L_C 32.512,15.24 r270 bottom
R9 "0R" RESC0603X03L_C 34.195,3.934 r90 bottom
R10 "0R" RESC0603X03L_C 31.254,2.359 r180 top
R11 "0R" RESC0603X03L_C 24.412,3.175 r0 top
R12 "100R" RESC0603X03L_C 35.763,28.445 r0 bottom
R13 "39R" RESC0603X03L_C 35.763,27.759 r0 bottom
R14 "39R" RESC0603X03L_C 35.763,27.073 r0 bottom
R15 "169R" RESC1005X04L 33.909,44.323 r0 bottom
R16 "7R15" RESC1005X04L 33.909,46.101 r0 bottom
R17 "11R" RESC1005X04L 33.909,43.434 r0 bottom
R18 "169R" RESC1005X04L 33.909,45.212 r0 bottom
R19 "7R15" RESC1005X04L 33.909,46.99 r0 bottom
R20 "11R" RESC1005X04L 33.909,42.545 r0 bottom
R21 "1k" RESC0603X03L_C 21.107,20.345 r180 bottom
R22 "4k7" RESC0603X03L_C 13.208,26.162 r0 bottom
R23 "4k7" RESC0603X03L_C 13.208,25.527 r0 bottom
R24 "0.1R" RESC1005X04L 8.153,34.696 r90 bottom
R25 "2R2" RESC1005X04L 13.564,34.417 r270 bottom
R26 "N.C." RESC0603X03L_C 12.83,34.814 r90 bottom
R27 "10k" RESC0603X03L_C 8.534,42.926 r0 bottom
R28 "10k" RESC0603X03L_C 8.56,42.088 r270 bottom
R29 "N.C." RESC0603X03L_C 11.967,35.144 r0 bottom
R30 "1M0" RESC0603X03L_C 11.967,34.534 r0 bottom
R31 "2R2" RESC1005X04L 16.205,39.065 r0 bottom
R32 "1M0" RESC0603X03L_C 10.468,42.084 r270 bottom
R33 "N.C." RESC0603X03L_C 11.078,42.084 r90 bottom
R34 "10k" RESC0603X03L_C 11.303,35.687 r0 bottom
R35 "10k" RESC0603X03L_C 11.687,42.084 r270 bottom
R36 "10k" RESC0603X03L_C 9.858,42.084 r90 bottom
R37 "10k" RESC0603X03L_C 9.249,42.084 r90 bottom
R38 "0R" RESC0603X03L_C 23.878,41.552 r90 bottom
R39 "100k" RESC0603X03L_C 5.359,16.307 r270 bottom
R40 "100k" RESC0603X03L_C 16.027,14.427 r90 bottom
R41 "1M0" RESC0603X03L_C 36.012,49.431 r270 bottom
R42 "1M0" RESC0603X03L_C 32.08,48.133 r90 bottom
R43 "1M0" RESC0603X03L_C 36.012,39.812 r90 bottom
R44 "1M0" RESC0603X03L_C 32.09,39.812 r90 bottom
R45 "1M0" RESC0603X03L_C 15.448,23.891 r270 bottom
R46 "1M0" RESC0603X03L_C 11.653,22.718 r90 bottom
R47 "1k" RESC0603X03L_C 12.014,26.848 r180 bottom
R48 "10M" RESC0603X03L_C 9.754,26.314 r270 bottom
SB1 "Solderbridge" Solderbridge_Shorted 9.144,33.096 r90 bottom net-tie
SB2 "Solderbridge" Solderbridge#1 7.112,33.096 r90 bottom
SB3 "Solderbridge" Solderbridge_Shorted 6.579,34.544 r0 top net-tie
SB4 "Solderbridge" Solderbridge_Shorted 9.119,34.544 r0 top net-tie
SB5 "Solderbridge" Solderbridge#2 30.734,34.29 r90 bottom
SB6 "Solderbridge" Solderbridge#3 29.337,34.29 r90 bottom
SB7 "Solderbridge" Solderbridge_Shorted 18.235,11.023 r90 bottom net-tie
SB8 "Solderbridge" Solderbridge_Shorted 19.378,11.023 r90 bottom net-tie
SB9 "Solderbridge" Solderbridge_Shorted 22.807,11.023 r90 bottom net-tie
SB10 "Solderbridge" Solderbridge_Shorted 20.521,11.023 r90 bottom net-tie
SB11 "Solderbridge" Solderbridge_Shorted 21.664,11.023 r90 bottom net-tie
ST1 "" "2 PIN STARPOINT"#1 17.653,24.714 r270 bottom net-tie
ST2 "" "2 PIN STARPOINT"#1 18.669,25.095 r0 bottom net-tie
ST3 "" "2 PIN STARPOINT"#1 18.669,25.603 r0 bottom net-tie
ST4 "" "2 PIN STARPOINT"#1 18.161,27.127 r90 bottom net-tie
ST5 "" "2 PIN STARPOINT"#1 18.669,26.111 r0 bottom net-tie
ST6 "" "2 PIN STARPOINT"#1 18.288,24.714 r270 bottom net-tie
ST7 "" "2 PIN STARPOINT"#1 17.272,35.814 r0 bottom net-tie
ST8 "" "2 PIN STARPOINT"#1 17.279,36.279 r0 bottom net-tie
ST9 "" "2 PIN STARPOINT"#1 16.993,35.535 r315 bottom net-tie
ST10 "" "2 PIN STARPOINT"#1 5.969,39.751 r180 bottom net-tie
ST11 "" "2 PIN STARPOINT"#2 13.056,39.091 r0 bottom net-tie
SW1 "Switch" Switch-Slide-RA-J-Lead-DPDT-8.5x3.5mm 2.475,39.62 r90 bottom locked
SW2 "AYZ0102AGRLC" AYZ0102AGRLC 3.1,17.1 r270 top locked
SW3 "PB SW" Switch-PB-6.2x6.3mm-SMD 28.6,25.3 r0 top locked
SW4 "PB SW" SW_TACTILE_2.6x3.0MM_4-LEAD 23.673,8.654 r90 top
TP1 "Ø1.0mm,SMD" TP_SMD_Ø1.0mm 9.982,18.136 r180 bottom
TP2 "Ø1.0mm,SMD" TP_SMD_Ø1.0mm 29.225,13.745 r90 bottom
TP3 "Ø1.0mm,SMD" TP_SMD_Ø1.0mm 29.225,12.245 r90 bottom
TP4 "Ø1.0mm,SMD" TP_SMD_Ø1.0mm 29.225,10.745 r0 bottom
TP5 "Ø1.0mm,SMD" TP_SMD_Ø1.0mm 15,20.125 r180 bottom
TP6 "Ø1.0mm,SMD" TP_SMD_Ø1.0mm 13,20.125 r180 bottom
TP7 "Ø1.0mm,SMD" TP_SMD_Ø1.0mm 26.975,34.29 r180 bottom
TP8 "Ø1.0mm,SMD" TP_SMD_Ø1.0mm 17.272,10.054 r0 top
TP9 "Ø1.5mm,SMD" TP_SMD_Ø1.5mm 3,31 r0 top locked
TP10 "Ø1.5mm,SMD" TP_SMD_Ø1.5mm 3,34 r0 top locked
TP11 "Ø1.5mm,SMD" TP_SMD_Ø1.5mm 11,34 r0 top locked
TP12 "Ø1.5mm,SMD" TP_SMD_Ø1.5mm 14,34 r0 top locked
TP13 "Ø1.5mm,SMD" TP_SMD_Ø1.5mm 11,48 r0 top locked
TP14 "Ø1.5mm,SMD" TP_SMD_Ø1.5mm 14,48 r0 top locked
TP15 "Ø1.5mm,SMD" TP_SMD_Ø1.5mm 27,9.5 r0 top locked
TP16 "Ø1.5mm,SMD" TP_SMD_Ø1.5mm 34,48 r0 top locked
TP17 "Ø1.5mm,SMD" TP_SMD_Ø1.5mm 17,34 r0 top
TP18 "Ø1.5mm,SMD" TP_SMD_Ø1.5mm 22,48 r0 top locked
TP19 "Ø1.5mm,SMD" TP_SMD_Ø1.5mm 25,48 r0 top locked
TP20 "Ø1.5mm,SMD" TP_SMD_Ø1.5mm 7,43 r180 bottom
TP21 "Ø1.5mm,SMD" TP_SMD_Ø1.5mm 7,41 r180 bottom
TP22 "Ø1.0mm,SMD" TP_SMD_Ø1.0mm 4.699,33.02 r180 bottom
TP23 "Ø1.0mm,SMD" TP_SMD_Ø1.0mm 2.794,33.02 r180 bottom
TP24 "Ø1.0mm,SMD" TP_SMD_Ø1.0mm 0.889,33.02 r180 bottom
TP25 "Ø1.0mm,SMD" TP_SMD_Ø1.0mm 13.25,3.75 r180 bottom
TP26 "Ø1.0mm,SMD" TP_SMD_Ø1.0mm 13.25,5.75 r180 bottom
TP27 "Ø1.5mm,SMD" TP_SMD_Ø1.5mm 4,8.5 r0 top locked
TP28 "Ø1.5mm,SMD" TP_SMD_Ø1.5mm 4,11 r0 top locked
TP29 "Ø1.5mm,SMD" TP_SMD_Ø1.5mm 7,8.5 r0 top locked
TP30 "Ø1.5mm,SMD" TP_SMD_Ø1.5mm 3,23.8 r0 top locked
TP31 "Ø1.5mm,SMD" TP_SMD_Ø1.5mm 3,26.8 r0 top locked
TP32 "Ø1.5mm,SMD" TP_SMD_Ø1.5mm 35.5,26.5 r0 top
TP33 "Ø1.5mm,SMD" TP_SMD_Ø1.5mm 21.5,26.5 r0 top
TP34 "Ø1.0mm,SMD" TP_SMD_Ø1.0mm 12.65,23.25 r90 top
TP35 "Ø1.0mm,SMD" TP_SMD_Ø1.0mm 15,23.25 r90 top
TP36 "Ø1.0mm,SMD" TP_SMD_Ø1.0mm 17.35,23.25 r90 top
TP37 "Ø1.0mm,SMD" TP_SMD_Ø1.0mm 7.9,21.5 r0 top
TP38 "Ø1.0mm,SMD" TP_SMD_Ø1.0mm 7.9,19 r0 top
U1 "nRF9160-SICA" LGA50P1600X1050X104-161N 17.706,16.477 r0 top locked
U2 "QM12038" UFQFN40P200X200X65_HS-15N#1 32.671,6.144 r0 top locked
U3 "QM12038" UFQFN40P200X200X65_HS-15N#2 32.671,3.781 r0 bottom locked
U4 "QM14501" QM14501 33.888,15.265 r90 top
U5 "NC7SV11L6X" DFN1410-6N 28.513,16.967 r0 bottom
U6 "nRF52840_CKAA" BGA94C35P10X10_352X356X50 18.322,6.151 r180 top locked
U7 "ADXL372" LGA50P322X300X114-16N 33.553,36.144 r180 bottom
U8 "ADXL362" LGA50P322X300X114-16N 27.635,39.065 r180 bottom
U9 "BME680" BME680 22.7,31.7 r0 bottom
U10 "BH1749NUC" WSON50P210X210X60_HS-9N 37.3,23.3 r0 bottom locked
U11 "ADP536x" BGA32C40P6X6_238X238X56 12.221,38.446 r180 bottom locked
U12 "FSA2466UMX" XQFN40P180X260X50-16N 16.358,12.471 r90 bottom
X1 "32MHz" BT-XTAL_2016 21.209,1.397 r180 top
X2 "32.768kHz" XTAL_1610 15.672,5.278 r90 top

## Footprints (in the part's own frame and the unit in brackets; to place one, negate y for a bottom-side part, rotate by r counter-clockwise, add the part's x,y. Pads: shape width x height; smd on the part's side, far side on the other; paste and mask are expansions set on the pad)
"2 PIN STARPOINT"#1 [mil]
  round 5 smd paste-3 mask-3: 1(-8,0) 2(8,0)
  Top Layer region: -11,3 11,3 11,-3 -11,-3
"2 PIN STARPOINT"#2 [mil]
  round 5 on Mid2 paste+0 mask+0: 1(-7,0) 2(7,0)
  Mid Layer 2 region: -11,6 11,6 11,-6 -11,-6
2450AT18D0100_STD-R [mm] "2450MHz Antenna"
  rect 1x0.6 smd mask+0.051: 1(1.5,-0.65) 2(-1.5,-0.65) 2(-1.5,0.65) 2(1.5,0.65)
  Top Layer pour cut-out: 2,-5.05 2,0.95 -2,0.95 -2,-5.05
  Bottom Layer pour cut-out: 2,-5.05 2,0.95 -2,0.95 -2,-5.05
  silkscreen extent -1.6,-0.8 1.6,0.8, body extent -1.61,-0.8 1.6,0.81, height 1.2
AYZ0102AGRLC [mm] "Slide Switches - SPDT, SMD, ON-ON"
  round 0.85 hole 0.85 unplated: 0(-1.5,0) 0(1.5,0)
  rect 1x1.2 smd: 1(-2.5,2.6) 2(0,2.6) 3(2.5,2.6)
  silkscreen extent -3.6,-2.5 3.6,1.5, body extent -3.6,-2.5 3.6,2.8, height 1.5
BGA32C40P6X6_238X238X56 [mm] "BGA, 32-Leads, Body 2.38x2.38mmx0.56mm, Pitch 0.40mm"
  round 0.21 smd: A1(-1,1) A2(-0.6,1) A3(-0.2,1) A4(0.2,1) A5(0.6,1) A6(1,1) B1(-1,0.6) B2(-0.6,0.6) B3(-0.2,0.6) B4(0.2,0.6) B5(0.6,0.6) B6(1,0.6) C1(-1,0.2) C2(-0.6,0.2) C5(0.6,0.2) C6(1,0.2) D1(-1,-0.2) D2(-0.6,-0.2) D5(0.6,-0.2) D6(1,-0.2) E1(-1,-0.6) E2(-0.6,-0.6) E3(-0.2,-0.6) E4(0.2,-0.6) E5(0.6,-0.6) E6(1,-0.6) F1(-1,-1) F2(-0.6,-1) F3(-0.2,-1) F4(0.2,-1) F5(0.6,-1) F6(1,-1)
  silkscreen extent -1.49,-1.25 1.25,1.49, body extent -1.19,-1.19 1.19,1.19, height 0.56
BGA94C35P10X10_352X356X50 [mm] "BGA, 94-Leads, Body 3.52x3.56mmx0.50mm, Pitch 0.35mm"
  round 0.2 smd mask+0.04: A1(-1.575,1.575) A2(-1.225,1.575) A3(-0.875,1.575) A4(-0.525,1.575) A5(-0.175,1.575) A6(0.175,1.575) A7(0.525,1.575) A8(0.875,1.575) A9(1.225,1.575) A10(1.575,1.575) B3(-0.875,1.225) B4(-0.525,1.225) B5(-0.175,1.225) B6(0.175,1.225) B7(0.525,1.225) B8(0.875,1.225) B9(1.225,1.225) B10(1.575,1.225) C1(-1.575,0.875) C2(-1.225,0.875) C4(-0.525,0.875) C5(-0.175,0.875) C6(0.175,0.875) C7(0.525,0.875) C8(0.875,0.875) C9(1.225,0.875) C10(1.575,0.875) D3(-0.875,0.525) D4(-0.525,0.525) D5(-0.175,0.525) D6(0.175,0.525) D7(0.525,0.525) D8(0.875,0.525) D9(1.225,0.525) D10(1.575,0.525) E1(-1.575,0.175) E2(-1.225,0.175) E3(-0.875,0.175) E4(-0.525,0.175) E5(-0.175,0.175) E6(0.175,0.175) E7(0.525,0.175) E8(0.875,0.175) E9(1.225,0.175) E10(1.575,0.175) F1(-1.575,-0.175) F2(-1.225,-0.175) F3(-0.875,-0.175) F4(-0.525,-0.175) F5(-0.175,-0.175) F6(0.175,-0.175) F7(0.525,-0.175) F8(0.875,-0.175) F9(1.225,-0.175) F10(1.575,-0.175) G1(-1.575,-0.525) G2(-1.225,-0.525) G3(-0.875,-0.525) G4(-0.525,-0.525) G5(-0.175,-0.525) G6(0.175,-0.525) G7(0.525,-0.525) G8(0.875,-0.525) G9(1.225,-0.525) G10(1.575,-0.525) H1(-1.575,-0.875) H2(-1.225,-0.875) H4(-0.525,-0.875) H5(-0.175,-0.875) H6(0.175,-0.875) H7(0.525,-0.875) H8(0.875,-0.875) H9(1.225,-0.875) H10(1.575,-0.875) J1(-1.575,-1.225) J2(-1.225,-1.225) J3(-0.875,-1.225) J4(-0.525,-1.225) J5(-0.175,-1.225) J6(0.175,-1.225) J7(0.525,-1.225) J8(0.875,-1.225) J9(1.225,-1.225) J10(1.575,-1.225) K1(-1.575,-1.575) K2(-1.225,-1.575) K3(-0.875,-1.575) K4(-0.525,-1.575) K5(-0.175,-1.575) K6(0.175,-1.575) K7(0.525,-1.575) K8(0.875,-1.575) K9(1.225,-1.575) K10(1.575,-1.575)
  silkscreen extent -2.22,-1.83 1.83,2.28, body extent -1.77,-1.76 1.77,1.84, height 0.47
BME680 [mm]
  rect 0.4x0.4 smd mask+0.1: 1(1.2,1.2) 2(1.2,0.4) 3(1.2,-0.4) 4(1.2,-1.2) 5(-1.2,-1.2) 6(-1.2,-0.4) 7(-1.2,0.4) 8(-1.2,1.2)
  silkscreen extent -1.58,-1.58 1.83,1.82, body extent -1.5,-1.5 1.5,1.5, height 0.93
BT-XTAL_2016 [mm] "Crystal 2.0 x 1.6 mm"
  rect 0.95x0.85 smd: 1(-0.725,-0.575) 2(0.725,-0.575) 3(0.725,0.575) 4(-0.725,0.575)
  silkscreen extent -1.08,-0.88 1.08,0.88, body extent -1.05,-0.85 1.05,0.85, height 0.56
Buzzer_SMD_7.5x7.5 [mm]
  rect 2.2x2.2 smd: 1(-3.1,3.1) 2(-3.1,-3.1)
  Top Layer region: 2,2 2,4.2 3.1,4.2 4.2,3.1 4.2,2
  Top Layer region: 2,-4.2 4.2,-4.2 4.2,-2 2,-2
  silkscreen extent -4.85,-4 3.9,4.95, body extent -3.76,-3.75 3.75,3.75, height 2.5
CAPC0603X03L_C [mm] "Chip Capacitor, 2-Leads, Body 0.6x0.3mm, IPC High Density"
  rect 0.27x0.3 smd: 1(-0.285,0) 2(0.285,0)
  silkscreen extent -0.49,-0.22 0.49,0.22, body extent -0.3,-0.15 0.31,0.15, height 0.3
CAPC1005X04L [mm] "Chip Capacitor, 2-Leads, Body 1.0x0.5mm, IPC High Density"
  rect 0.6x0.5 smd: 1(-0.5,0) 2(0.5,0)
  silkscreen extent -0.9,-0.35 0.9,0.35, body extent -0.51,-0.25 0.51,0.25, height 0.5
CAPC1608X06L [mm] "Chip Capacitor, 2-Leads, Body 1.6x0.8mm, IPC High Density"
  rect 0.75x0.8 smd: 1(-0.675,0) 2(0.675,0)
  silkscreen extent -1.18,-0.5 1.17,0.5, body extent -0.8,-0.43 0.8,0.43, height 0.8
CAPC2012X11L [mm] "Chip Capacitor, 2-Leads, Body 2.0x1.3mm, IPC High Density"
  rect 1.1x1.4 smd: 1(-0.75,0) 2(0.75,0)
  silkscreen extent -1.43,-0.8 1.42,0.8, body extent -1,-0.62 1,0.63, height 0.77
CM1402 [mm]
  round 0.25 smd mask+0.05: A1(-0.75,0.435) A2(-0.25,0.435) A3(0.25,0.435) A4(0.75,0.435) B1(-0.5,0) B2(0.5,0) C1(-0.75,-0.435) C2(-0.25,-0.435) C3(0.25,-0.435) C4(0.75,-0.435)
  silkscreen extent -1.28,-0.73 1.04,0.96, body extent -0.98,-0.66 0.98,0.66, height 0.72
COAXIAL-SWF [mm]
  rect 0.5x0.58 smd: 1(0,1.16) 3(0,-1.16)
  rect 0.75x0.8 smd: 2(-1.025,-0.95) 2(-1.025,0.95) 2(1.025,-0.95) 2(1.025,0.95)
  Top Layer pour cut-out: 0.65,-0.55 -0.65,-0.55 -0.65,-1.35 0.65,-1.35
  Top Layer pour cut-out: -0.65,0.55 0.65,0.55 0.65,1.35 -0.65,1.35
  silkscreen extent -1.25,-1.25 1.25,1.25, body extent -1.26,-1.3 1.26,1.3, height 1.55
DFN65P100X40-3L [mm] "DFN, 3-Leads, Body 0.60x1.00mm, Pitch 0.65mm, IPC High Density"
  rect 0.4x0.25 smd: 1(-0.35,0.225) 2(-0.35,-0.225)
  rect 0.4x0.7 smd: 3(0.35,0)
  silkscreen extent -0.57,0.58 -0.48,0.67, body extent -0.52,-0.32 0.53,0.32, height 0.4
DFN65P200X200X80_HS-6N [mm] "DFN, 6-Leads, Body 2.00x2.00mm, Pitch 0.65mm, IPC Medium Density"
  rect 0.55x0.42 smd mask+0.055: 1(-0.945,0.65) 2(-0.945,0) 3(-0.945,-0.65) 4(0.945,-0.65) 5(0.945,0) 6(0.945,0.65)
  rect 0.92x0.71 smd mask+0.055: 3(0,-0.475) 6(0,0.475)
  silkscreen extent -1.47,-1.08 1.08,1.27, body extent -1.03,-1.03 1.02,1.02, height 0.8
DFN1410-6N [mm] "PSON, 6-Leads, Body 1,40x1,00mm, Pitch 0,50mm, IPC Medium Density"
  rect 0.525x0.25 smd mask+0.05: 1(-0.363,0.5) 2(-0.363,0) 3(-0.363,-0.5) 4(0.363,-0.5) 5(0.363,0) 6(0.363,0.5)
  silkscreen extent -0.76,-0.8 0.48,0.96, body extent -0.53,-0.73 0.53,0.72, height 0.4
Fiducial_Round-Square [mm] "Fiducial Mark"
  rect 1x1 smd paste-10 mask+0.5: 0(0,0)
  round 1 smd far side paste-10 mask+0.5: 0(0,0)
  Top Layer keep-out lines w0.01: -1,-1 -1,1 1,1 1,-1 -1,-1
  Bottom Layer keep-out circle w0.01: c0,0 r1
FPC_05P-0.5mm-RA-SMD [mm] "FPC, 5-Leads, Pitch 0,5mm"
  rect 0.6x2.6 smd: 0(-0.9,-2.3) 0(2.9,-2.3)
  rect 0.3x0.8 smd mask+0.05: 1(0,0) 2(0.5,0) 3(1,0) 4(1.5,0) 5(2,0)
  silkscreen extent -1.38,-3.93 3.38,0.08, body extent -1.3,-3.85 3.3,0.2, height 1.2
FR01-S4-210_DF [mm]
  rect 2x3 smd: 0(0,0) 2(10.5,0) 4(-10.5,0)
  rect 3x3 smd: 1(13.5,0) 3(-13.5,0)
  Top Layer region: 15,-2.243 15,-0.312 14,-0.312 14,-2.243
  Top Layer region: 14,-2.547 15,-2.547 15,-10.022 14,-10.022
  Top Layer region: 13,-0.5 12,-0.5 12,-4 13,-4
  Top Layer region: 11.5,-0.5 10.5,-0.5 10.5,-4 11.5,-4
  Top Layer region: -12,-0.5 -13,-0.5 -13,-4 -12,-4
  Top Layer region: -10.5,-0.5 -11.5,-0.5 -11.5,-4 -10.5,-4
  Top Layer pour cut-out: -25,2 15.4,2 15.4,-10.5 -25,-10.5
  Top Layer region: 15,-9.2 15,-10.2 13,-10.2 13,-9.2
  Mid Layer 1 pour cut-out: -25,2 15.4,2 15.4,-10.5 -25,-10.5
  Mid Layer 2 pour cut-out: -25,2 15.4,2 15.4,-10.5 -25,-10.5
  Bottom Layer pour cut-out: -25,2 15.4,2 15.4,-10.5 -25,-10.5
  silkscreen extent -15,-1.6 15,1.6, body extent -15,-1.5 15,1.5, height 1
HDR_2x3_TH_2.00MM-NC [mm]
  rect 1.4x1.4 hole 0.9: 1(-2,-1)
  round 1.4 hole 0.9: 2(-2,1) 3(0,-1) 4(0,1) 5(2,-1) 6(2,1)
  silkscreen extent -3,-2 3,2
HDR_2x5-SMD-1.27mm-ANG [mm] "Pin Header Angled, 1.27mm SMD, FTSH-105 series, \"SWD\" version"
  round 1.02 hole 1.02 unplated: 0(-1.905,-4.32) 0(1.905,-4.32)
  rect 0.76x2.03 smd: 1(-2.54,-1.525) 2(-2.54,1.525) 3(-1.27,-1.525) 4(-1.27,1.525) 5(0,-1.525) 6(0,1.525) 7(1.27,-1.525) 8(1.27,1.525) 9(2.54,-1.525) 10(2.54,1.525)
  silkscreen extent -3.17,-5.57 3.17,-3.07, body extent -3.18,-8.63 3.17,2.27, height 3.41
HDR_2x5_TH_2.00MM-NC [mm]
  rect 1.4x1.4 hole 0.9: 1(-4,-1)
  round 1.4 hole 0.9: 2(-4,1) 3(-2,-1) 4(-2,1) 5(0,-1) 6(0,1) 7(2,-1) 8(2,1) 9(4,-1) 10(4,1)
  silkscreen extent -5,-2 5,2
HOLE_NP_3MM [mm] "Regular 3mm non-plated hole"
  round 3 hole 3 unplated paste+0 mask+0: ""(0,0)
  silkscreen extent -1.7,-1.7 1.7,1.7
INDC0603X03L_C [mm] "Chip Inductor, 2-Leads, Body 0.6x0.3mm, IPC High Density"
  rect 0.27x0.3 smd: 1(-0.285,0) 2(0.285,0)
  silkscreen extent -0.49,-0.22 0.49,0.22, body extent -0.31,-0.16 0.31,0.16, height 0.26
INDC1005X04L [mm] "Chip Inductor, 2-Leads, Body 1.0x0.5mm, IPC High Density"
  rect 0.65x0.5 smd: 1(-0.475,0) 2(0.475,0)
  silkscreen extent -0.9,-0.35 0.9,0.35, body extent -0.5,-0.3 0.5,0.3, height 0.5
INDC1608X06L [mm] "Chip Inductor, 2-Leads, Body 1.6x0.8mm, IPC High Density"
  rect 0.75x0.8 smd: 1(-0.675,0) 2(0.675,0)
  silkscreen extent -1.17,-0.5 1.17,0.5, body extent -0.8,-0.48 0.8,0.48, height 0.8
INDC2016X18N [mm] "Chip Inductor, 2-Leads, Body 2,00x1,60mm, IPC Medium Density"
  rect 1x1.8 smd: 1(-0.8,0) 2(1,0)
  silkscreen extent -0.15,-0.77 0.35,0.77, body extent -0.9,-0.8 1.1,0.8, height 1
LED_RGB_0606 [mm]
  rect 0.65x0.85 smd paste+0: 1(-0.425,0.725) 2(0.425,0.725) 3(0.425,-0.725) 4(-0.425,-0.725)
  silkscreen extent -0.75,-0.8 0.75,0.8, body extent -0.75,-0.8 0.75,0.8, height 0.35
LGA50P322X300X114-16N [mm] "LGA, 16-Leads, Body 3.25x3.00mm, Pitch 0.50mm, IPC Medium Density"
  rect 0.925x0.3 smd mask+0.06: 1(-1.288,1) 2(-1.288,0.5) 3(-1.288,0) 4(-1.288,-0.5) 5(-1.288,-1) 9(1.288,-1) 10(1.288,-0.5) 11(1.288,0) 12(1.288,0.5) 13(1.288,1)
  rect 0.3x0.8 smd mask+0.06: 6(-0.5,-1.275) 7(0,-1.275) 8(0.5,-1.275) 14(0.5,1.275) 15(0,1.275) 16(-0.5,1.275)
  silkscreen extent -2.5,-1.62 1.72,1.67, body extent -1.65,-1.55 1.65,1.55, height 1.14
LGA50P1600X1050X104-161N [mm]
  rect 0.54x0.54 smd mask+0.05: 1(-7.87,5.12) 21(-7.87,-5.12) 52(7.87,-5.12) 72(7.87,5.12)
  rect 0.54x0.3 smd mask+0.05: 2(-7.87,4.5) 3(-7.87,4) 4(-7.87,3.5) 5(-7.87,3) 6(-7.87,2.5) 7(-7.87,2) 8(-7.87,1.5) 9(-7.87,1) 10(-7.87,0.5) 11(-7.87,0) 12(-7.87,-0.5) 13(-7.87,-1) 14(-7.87,-1.5) 15(-7.87,-2) 16(-7.87,-2.5) 17(-7.87,-3) 18(-7.87,-3.5) 19(-7.87,-4) 20(-7.87,-4.5) 53(7.87,-4.5) 54(7.87,-4) 55(7.87,-3.5) 56(7.87,-3) 57(7.87,-2.5) 58(7.87,-2) 59(7.87,-1.5) 60(7.87,-1) 61(7.87,-0.5) 62(7.87,0) 63(7.87,0.5) 64(7.87,1) 65(7.87,1.5) 66(7.87,2) 67(7.87,2.5) 68(7.87,3) 69(7.87,3.5) 70(7.87,4) 71(7.87,4.5)
  rect 0.3x0.54 smd mask+0.05: 22(-7.25,-5.12) 23(-6.75,-5.12) 24(-6.25,-5.12) 25(-5.75,-5.12) 26(-5.25,-5.12) 27(-4.75,-5.12) 28(-4.25,-5.12) 29(-3.75,-5.12) 30(-3.25,-5.12) 31(-2.75,-5.12) 32(-2.25,-5.12) 33(-1.75,-5.12) 34(-1.25,-5.12) 35(-0.75,-5.12) 36(-0.25,-5.12) 37(0.25,-5.12) 38(0.75,-5.12) 39(1.25,-5.12) 40(1.75,-5.12) 41(2.25,-5.12) 42(2.75,-5.12) 43(3.25,-5.12) 44(3.75,-5.12) 45(4.25,-5.12) 46(4.75,-5.12) 47(5.25,-5.12) 48(5.75,-5.12) 49(6.25,-5.12) 50(6.75,-5.12) 51(7.25,-5.12) 73(7.25,5.12) 74(6.75,5.12) 75(6.25,5.12) 76(5.75,5.12) 77(5.25,5.12) 78(4.75,5.12) 79(4.25,5.12) 80(3.75,5.12) 81(3.25,5.12) 82(2.75,5.12) 83(2.25,5.12) 84(1.75,5.12) 85(1.25,5.12) 86(0.75,5.12) 87(0.25,5.12) 88(-0.25,5.12) 89(-0.75,5.12) 90(-1.25,5.12) 91(-1.75,5.12) 92(-2.25,5.12) 93(-2.75,5.12) 94(-3.25,5.12) 95(-3.75,5.12) 96(-4.25,5.12) 97(-4.75,5.12) 98(-5.25,5.12) 99(-5.75,5.12) 100(-6.25,5.12) 101(-6.75,5.12) 102(-7.25,5.12)
  rect 0.8x0.8 smd mask+0.05: 103(-6,-3.2) 103(-6,-1.6) 103(-6,0) 103(-6,1.6) 103(-6,3.2) 103(-4,-3.2) 103(-4,-1.6) 103(-4,0) 103(-4,1.6) 103(-4,3.2) 103(-2,-3.2) 103(-2,-1.6) 103(-2,0) 103(-2,1.6) 103(-2,3.2) 103(0,-3.2) 103(0,-1.6) 103(0,0) 103(0,1.6) 103(0,3.2) 103(2,-3.2) 103(2,-1.6) 103(2,0) 103(2,1.6) 103(2,3.2) 103(4,-3.2) 103(4,-1.6) 103(4,0) 103(4,1.6) 103(4,3.2) 103(6,-3.2) 103(6,-1.6) 103(6,0) 103(6,1.6) 103(6,3.2)
  rect 0.3x0.3 smd mask+0.05: 104(-5.75,-4.35) 105(-5.25,-4.35) 106(-4.75,-4.35) 107(-4.25,-4.35) 108(-1.75,-4.35) 109(-1.25,-4.35) 110(-0.75,-4.35) 111(-0.25,-4.35) 112(3.25,-4.35) 113(3.75,-4.35) 114(4.25,-4.35) 115(4.75,-4.35) 116(4.75,4.35) 117(4.25,4.35) 118(3.75,4.35) 119(3.25,4.35) 120(-0.25,4.35) 121(-0.75,4.35) 122(-1.25,4.35) 123(-1.75,4.35) 124(-4.25,4.35) 125(-4.75,4.35) 126(-5.25,4.35) 127(-5.75,4.35)
  Top Layer pour cut-out: -8.15,5.4 8.15,5.4 8.15,-5.4 -8.15,-5.4
  silkscreen extent -8.75,-5.5 8.25,6, body extent -8.05,-5.3 8.05,5.3, height 1.2
LIST_1x2-NC [mm] "Pin List, 2.54mm through hole"
  rect 1.5x1.5 hole 0.9: 1(-1.27,0)
  round 1.5 hole 0.9: 2(1.27,0)
  silkscreen extent -2.54,-1.27 2.54,1.27
LXES03AAA1-154 [mm]
  rect 0.275x0.3 smd: 1(-0.262,0) 2(0.262,0)
  silkscreen extent -0.47,-0.23 0.47,0.23, body extent -0.31,-0.16 0.31,0.16, height 0.23
MSL0104 [mm]
  rect 1.06x1.58 smd paste+0: 1(-2.95,0.3) 1(2.95,0.3)
  rect 0.6x2.18 smd paste+0: 2(1.8,0) 3(0.9,0) 4(0,0) 5(-0.9,0) 6(-1.8,0)
  silkscreen extent -3.2,1.3 3.2,1.75, body extent -3.45,-0.4 3.45,1.78, height 2.15
QM14501 [mm]
  rect 0.35x0.35 smd mask+0.065: 1(-1.375,0.775) 2(-1.375,0) 3(-1.375,-0.775) 4(-0.683,-0.775) 5(0.009,-0.775) 6(0.701,-0.775) 7(1.375,-0.775) 8(1.375,0) 9(1.375,0.775) 10(0.701,0.775) 11(0.009,0.775) 12(-0.683,0.775)
  Top Layer region: -0.208,-0.6 0.9,-0.6 0.9,0.6 -0.208,0.6
  Top Layer region: -0.208,0.474 1.55,0.474 1.55,0.95 -0.208,0.95
  Top Layer region: -0.733,-0.775 -0.633,-0.775 -0.633,-0.15 -0.733,-0.15
  Top Layer region: -1.551,-0.3 -0.151,-0.3 -0.151,0.3 -1.551,0.3
  Top Layer region: -0.208,-0.95 1.55,-0.95 1.55,-0.474 -0.208,-0.474
  silkscreen extent -1.94,-1.11 1.71,1.34, body extent -1.7,-1.1 1.7,1.1, height 1.01
RESC0603X03L_C [mm] "Chip Resistor, 2-Leads, Body 0.6x0.3mm, IPC High Density"
  rect 0.27x0.3 smd: 1(-0.285,0) 2(0.285,0)
  silkscreen extent -0.49,-0.22 0.49,0.22, body extent -0.3,-0.15 0.3,0.15, height 0.23
RESC1005X04L [mm] "Chip Resistor, 2-Leads, Body 1.0x0.5mm, IPC High Density"
  rect 0.6x0.55 smd: 1(-0.5,0) 2(0.5,0)
  silkscreen extent -0.87,-0.38 0.87,0.38, body extent -0.5,-0.25 0.5,0.25, height 0.3
SAFFB2G45MA0F0A [mm] "SOT23, 5-Leads, Body 2,90x2,80mm, Pitch 0,95mm, IPC Medium Density"
  rect 0.2x0.25 smd: 1(-0.4,0) 2(0,-0.25) 3(0.4,-0.25) 4(0.4,0.25) 5(0,0.25)
  silkscreen extent -0.81,-0.71 0.61,0.51, body extent -0.55,-0.45 0.55,0.45, height 0.5
SF72S006VBAR2500 [mm] "SOT23, 5-Leads, Body 2,90x2,80mm, Pitch 0,95mm, IPC Medium Density"
  rect 0.45x1.9 smd: 0(-11.175,6.75) 0(0,6.75)
  rect 0.45x2.9 smd: 0(-11.175,1.9) 0(0,1.9)
  rect 0.75x0.7 smd: 0(-10.675,10.9)
  rect 1.4x0.5 smd: 0(-8.78,13.85) 0(-4.38,13.85)
  rect 0.3x0.6 smd: 0(-7.8,0.75) 0(-5.36,0.75)
  rect 0.45x2.4 smd: 0(0,11.9)
  rect 0.9x0.7 smd: C1(-4.14,2.6) C2(-6.58,2.6) C3(-9.02,2.6) C5(-4.04,5.77) C6(-6.58,5.77) C7(-9.12,5.77)
  rect 0.6x0.6 smd: CSW(-10.95,9.1)
  rect 1.2x0.65 smd: DSW(-7.13,12.775)
  Top Layer pour cut-out: -8.407,13.106 -3.48,13.106 -3.48,9.855 -8.407,9.855
  Top Layer pour cut-out: -10.084,9.5 -3.073,9.5 -3.073,-0.025 -10.084,-0.025
  silkscreen extent -11.3,-0.67 0.67,14.53, body extent -11.2,0.05 0.02,14.4, height 1.25
SM03B-SRSS-TB [mm] "JST, SH connector, side entry SMD, 1mm pitch"
  rect 1.2x1.8 smd: 0(-2.6,-3.875) 0(2.6,-3.875)
  rect 0.6x1.55 smd: 1(-1,0) 2(0,0) 3(1,0)
  silkscreen extent -2.57,-4.68 2.58,-0.3, body extent -2.5,-4.61 2.5,0.34, height 2.95
SOD-123-DIODE [mil]
  rect 36x48 smd: 1(-70,0) 2(70,0)
  silkscreen extent -58,-36 58,36, body extent -77,-33 75,33, height 56
SODFL100X40-2N [mm] "SODFL, 2-Leads, Body 0.60x1.00mm, IPC Medium Density"
  rect 0.36x0.25 smd: 1(-0.42,0) 2(0.42,0)
  silkscreen extent -0.7,-0.35 0.5,0.5, body extent -0.5,-0.33 0.5,0.32, height 0.4
Solderbridge#1 [mm]
  round 0.2 smd paste-10: 1(-0.312,0) 2(0.312,0)
  Top Layer region: -0.077,-0.432 -0.152,-0.505 -0.271,-0.467 -0.335,-0.424 -0.409,-0.351 -0.462,-0.292 -0.521,-0.193 -0.549,-0.099 -0.544,0.122 -0.518,0.193 -0.434,0.33 -0.351,0.411 -0.259,0.469 -0.157,0.5 -0.107,0.483 -0.077,0.43
  Top Layer region: 0.077,0.432 0.152,0.505 0.271,0.467 0.335,0.424 0.409,0.351 0.462,0.292 0.521,0.193 0.549,0.099 0.544,-0.122 0.518,-0.193 0.434,-0.33 0.351,-0.411 0.259,-0.469 0.157,-0.5 0.107,-0.483 0.077,-0.43
  Top Layer lines w0.152: -0.153,-0.431 cw(c-0.042,0) -0.456,0.162 cw(c-0.042,0) -0.153,0.431 ; 0.153,-0.431 ccw(c0.042,0) 0.457,-0.16 ccw(c0.042,0) 0.487,0 ccw(c0.042,0) 0.153,0.431
Solderbridge#2 [mm]
  round 0.2 smd paste-10: 1(-0.312,0) 2(0.312,0)
  Top Layer region: 0.077,0.432 0.152,0.505 0.271,0.467 0.335,0.424 0.409,0.351 0.462,0.292 0.521,0.193 0.549,0.099 0.544,-0.122 0.518,-0.193 0.434,-0.33 0.351,-0.411 0.259,-0.469 0.157,-0.5 0.107,-0.483 0.077,-0.43
  Top Layer region: -0.077,-0.432 -0.152,-0.505 -0.271,-0.467 -0.335,-0.424 -0.409,-0.351 -0.462,-0.292 -0.521,-0.193 -0.549,-0.099 -0.544,0.122 -0.518,0.193 -0.434,0.33 -0.351,0.411 -0.259,0.469 -0.157,0.5 -0.107,0.483 -0.077,0.43
  Top Layer lines w0.152: -0.153,-0.431 cw(c-0.042,0) -0.254,-0.391 cw(c-0.042,0) -0.258,-0.389 cw(c-0.042,0) -0.258,0.389 cw(c-0.042,0) -0.254,0.391 cw(c-0.042,0) -0.153,0.431 ; 0.153,-0.431 ccw(c0.042,0) 0.312,0.353 ccw(c0.042,0) 0.153,0.431
Solderbridge#3 [mm]
  round 0.2 smd paste-10: 1(-0.312,0) 2(0.312,0)
  Top Layer region: -0.077,-0.432 -0.152,-0.505 -0.271,-0.467 -0.335,-0.424 -0.409,-0.351 -0.462,-0.292 -0.521,-0.193 -0.549,-0.099 -0.544,0.122 -0.518,0.193 -0.434,0.33 -0.351,0.411 -0.259,0.469 -0.157,0.5 -0.107,0.483 -0.077,0.43
  Top Layer region: 0.077,0.432 0.152,0.505 0.271,0.467 0.335,0.424 0.409,0.351 0.462,0.292 0.521,0.193 0.549,0.099 0.544,-0.122 0.518,-0.193 0.434,-0.33 0.351,-0.411 0.259,-0.469 0.157,-0.5 0.107,-0.483 0.077,-0.43
  Top Layer lines w0.152: -0.153,-0.431 cw(c-0.042,0) -0.254,-0.391 cw(c-0.042,0) -0.258,-0.389 cw(c-0.042,0) -0.258,0.389 cw(c-0.042,0) -0.254,0.391 cw(c-0.042,0) -0.153,0.431 ; 0.153,-0.431 ccw(c0.042,0) 0.312,-0.353 ccw(c0.042,0) 0.381,-0.288 ccw(c0.042,0) 0.461,-0.149 ccw(c0.042,0) 0.153,0.431
Solderbridge_Shorted [mm]
  round 0.2 smd paste-10: 1(-0.338,0) 2(0.338,0)
  Top Layer region: 0.102,0.432 0.178,0.505 0.296,0.467 0.361,0.424 0.434,0.351 0.488,0.292 0.546,0.193 0.574,0.099 0.569,-0.122 0.544,-0.193 0.46,-0.33 0.376,-0.411 0.284,-0.469 0.183,-0.5 0.132,-0.483 0.102,-0.43
  Top Layer region: -0.102,-0.432 -0.178,-0.505 -0.296,-0.467 -0.361,-0.424 -0.434,-0.351 -0.488,-0.292 -0.546,-0.193 -0.574,-0.099 -0.569,0.122 -0.544,0.193 -0.46,0.33 -0.376,0.411 -0.284,0.469 -0.183,0.5 -0.132,0.483 -0.102,0.43
  Top Layer lines w0.152: -0.178,-0.431 cw(c-0.068,0) -0.178,0.431 ; 0.178,-0.431 ccw(c0.068,0) 0.178,0.431
  Top Layer lines w0.203: -0.338,0 0.338,0
SOT-23a [mil] "SOT-23 footprint"
  rect 30x40 smd: 1(0,0) 2(74.8,0) 3(37.4,82.68)
  silkscreen extent -39,-4 94,79, body extent -20,-5 95,87, height 39
SW_TACTILE_2.6x3.0MM_4-LEAD [mm] "2.6×3.0mm TACT Switch, without ground connector"
  rect 0.65x0.7 smd: 1(-1.475,0.95) 1(1.475,0.95) 2(-1.475,-0.95) 2(1.475,-0.95)
  Top Layer keep-out region: -0.9,-1.3 0.9,-1.3 0.9,1.3 -0.9,1.3
  silkscreen extent -1.5,-1.3 1.5,1.3, body extent -1.6,-1.3 1.6,1.3, height 0.65
Switch-PB-6.2x6.3mm-SMD [mm] "6.2×6.5mm TACT Switch, without ground connector"
  rect 2.75x1.39 smd: 1(-3.375,2)
  rect 2.75x1.4 smd: 1(3.375,2) 2(-3.375,-2) 2(3.375,-2)
  silkscreen extent -3,-3 3,3, body extent -4,-3 4,3.3, height 3.1
Switch-Slide-RA-J-Lead-DPDT-8.5x3.5mm [mm] "Slide Switches - DPDT, SMD, ON-ON"
  round 0.9 hole 0.9 unplated mask+0: 0(-3.4,0) 0(3.4,0)
  rect 1x1.6 smd: 1(-2.5,-1.4) 2(0,-1.4) 3(2.5,-1.4) 4(-2.5,1.4) 5(0,1.4) 6(2.5,1.4)
  silkscreen extent -4.5,-3.8 4.5,1.75, body extent -4.25,-3.75 4.25,1.75, height 3.5
TP_SMD_Ø1.0mm [mm]
  round 1 smd paste-5: 1(0,0)
  silkscreen extent -0.76,-0.76 0.76,0.76
TP_SMD_Ø1.5mm [mm]
  round 1.5 smd paste-5: 1(0,0)
  silkscreen extent -0.95,-0.95 0.95,0.95
UFQFN40P200X200X65_HS-15N#1 [mm] "UFQFN, 14-Leads, Body 2.00x2.00mm, Pitch 0.45mm/0.40mm, Thermal Pad 1.00x1.00mm, IPC Medium Density"
  rect 0.23x0.25 smd paste-1 mask+0.06: 1(-0.845,0.675) 2(-0.845,0.225) 3(-0.845,-0.225) 4(-0.845,-0.675) 8(0.845,-0.675) 9(0.845,-0.225) 10(0.845,0.225) 11(0.845,0.675)
  rect 0.25x0.23 smd paste-1 mask+0.06: 5(-0.4,-0.845) 6(0,-0.845) 7(0.4,-0.845) 12(0.4,0.845) 13(0,0.845) 14(-0.4,0.845)
  rect 1x1 smd paste-1 mask+0.06: 15(0,0)
  oval 0.23x0.25 on Top Paste: ""(-0.845,0.225) ""(-0.845,-0.675) ""(-0.845,-0.225) ""(-0.845,0.675) ""(0.845,-0.675) ""(0.845,-0.225) ""(0.845,0.225) ""(0.845,0.675)
  oval 0.25x0.23 on Top Paste: ""(-0.4,-0.845) ""(-0.4,0.845) ""(0,-0.845) ""(0,0.845) ""(0.4,-0.845) ""(0.4,0.845)
  rrect25% 0.85x0.85 on Top Paste: ""(0,0)
  silkscreen extent -1.37,-1.05 1.05,1.37, body extent -1.02,-1.02 1.03,1.03, height 0.65
UFQFN40P200X200X65_HS-15N#2 [mm] "UFQFN, 14-Leads, Body 2.00x2.00mm, Pitch 0.45mm/0.40mm, Thermal Pad 1.00x1.00mm, IPC Medium Density"
  rect 0.23x0.25 smd paste-1 mask+0.06: 1(-0.845,0.675) 2(-0.845,0.225) 3(-0.845,-0.225) 4(-0.845,-0.675) 8(0.845,-0.675) 9(0.845,-0.225) 10(0.845,0.225) 11(0.845,0.675)
  rect 0.25x0.23 smd paste-1 mask+0.06: 5(-0.4,-0.845) 6(0,-0.845) 7(0.4,-0.845) 12(0.4,0.845) 13(0,0.845) 14(-0.4,0.845)
  rect 1x1 smd paste-1 mask+0.06: 15(0,0)
  oval 0.23x0.25 on Bottom Paste: ""(-0.845,0.225) ""(-0.845,-0.675) ""(-0.845,-0.225) ""(-0.845,0.675) ""(0.845,-0.675) ""(0.845,-0.225) ""(0.845,0.225) ""(0.845,0.675)
  oval 0.25x0.23 on Bottom Paste: ""(-0.4,-0.845) ""(-0.4,0.845) ""(0,-0.845) ""(0,0.845) ""(0.4,-0.845) ""(0.4,0.845)
  rrect25% 0.85x0.85 on Bottom Paste: ""(0,0)
  silkscreen extent -1.37,-1.05 1.05,1.37, body extent -1.02,-1.02 1.03,1.03, height 0.65
USB-Micro-B-RA-SMD-PiP [mm] "Micro USB B SMT"
  rect 1.35x0.4 smd: 1(0,1.3) 2(0,0.65) 3(0,0) 4(0,-0.65) 5(0,-1.3)
  oval 1.6x0.9 hole 0.5 slot 1.2 at 0 deg: 6(-2.675,-3.3) 6(-2.675,3.3)
  oval 2x1.5 on Bottom Paste: 6(-2.675,-3.3) 6(-2.675,3.3)
  rect 1.55x1.9 smd: 6(-2.675,-1.2) 6(-2.675,1.2)
  rect 1.4x1.6 smd: 6(-0.225,-3.2) 6(-0.225,3.2)
  silkscreen extent -4.75,-3.75 0.25,3.75, body extent -5.28,-4.1 0.15,4.1, height 2.72
WSON50P210X210X60_HS-9N [mm] "WSON, 8-Leads, Body 2.10x2.10mm, Pitch 0.50mm, Thermal Pad 0.75x1.50mm, IPC Medium Density"
  rect 0.65x0.25 smd: 1(-1.075,0.75) 2(-1.075,0.25) 3(-1.075,-0.25) 4(-1.075,-0.75) 5(1.075,-0.75) 6(1.075,-0.25) 7(1.075,0.25) 8(1.075,0.75)
  rect 0.75x1.5 smd: 9(0,0)
  silkscreen extent -1.67,-1.15 1.1,1.67, body extent -1.1,-1.05 1.1,1.05, height 0.6
XQFN40P180X260X50-16N [mm] "QFN, 16-Leads, Body 1.80x2.60mm, Pitch 0.40mm, IPC Medium Density"
  oval 0.65x0.22 smd paste-0.02 mask+0.04: 1(-0.825,0.6) 2(-0.825,0.2) 3(-0.825,-0.2) 4(-0.825,-0.6) 9(0.825,-0.6) 10(0.825,-0.2) 11(0.825,0.2) 12(0.825,0.6)
  oval 0.22x0.65 smd paste-0.02 mask+0.04: 5(-0.6,-1.225) 6(-0.2,-1.225) 7(0.2,-1.225) 8(0.6,-1.225) 13(0.6,1.225) 14(0.2,1.225) 15(-0.2,1.225) 16(-0.6,1.225)
  silkscreen extent -1.45,-1.4 1,1.4, body extent -0.91,-1.31 0.91,1.31, height 0.55
XTAL_1610 [mm] "XTAL SMD 1.6 x 1.0 mm"
  rect 0.5x1 smd: 1(-0.55,0) 2(0.55,0)
  silkscreen extent -0.15,-0.5 0.15,0.5, body extent -0.8,-0.5 0.8,0.5, height 0.5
